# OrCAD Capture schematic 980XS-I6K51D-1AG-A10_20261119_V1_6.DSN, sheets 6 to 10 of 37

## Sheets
6 P0061_S6_POWER: size A2
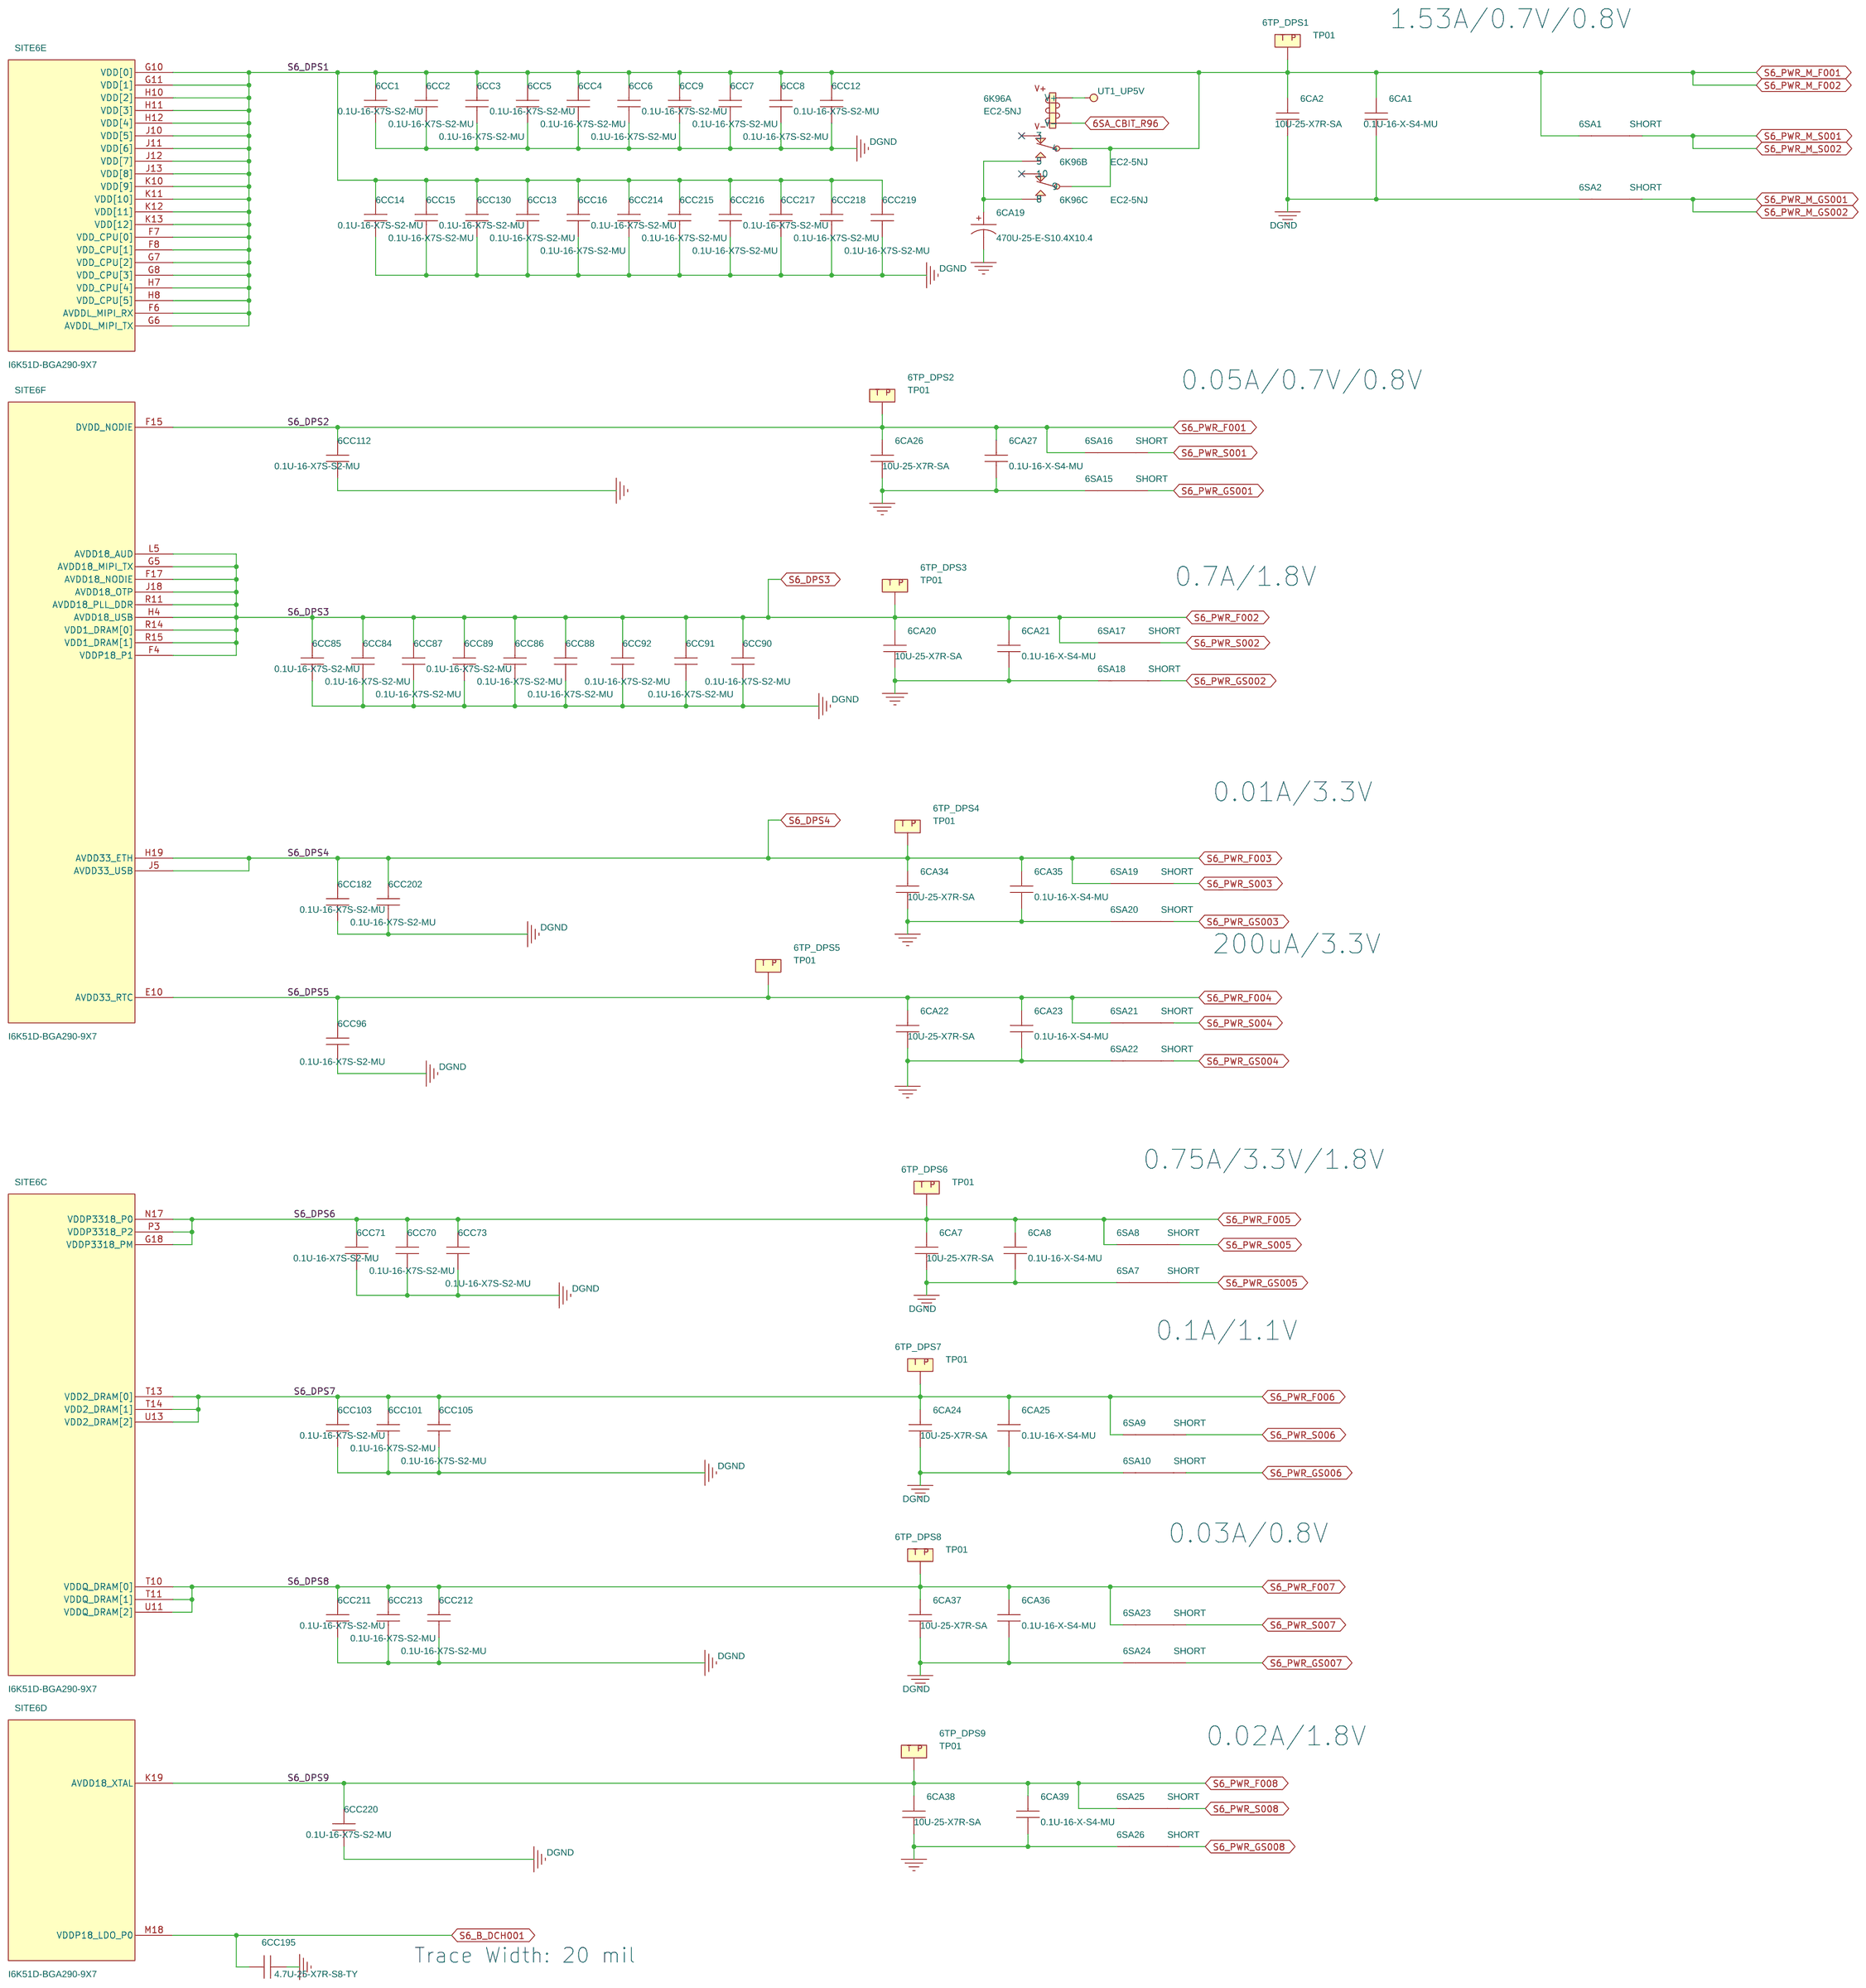
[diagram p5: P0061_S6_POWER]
7 P0053_S5_MIPI: size A2
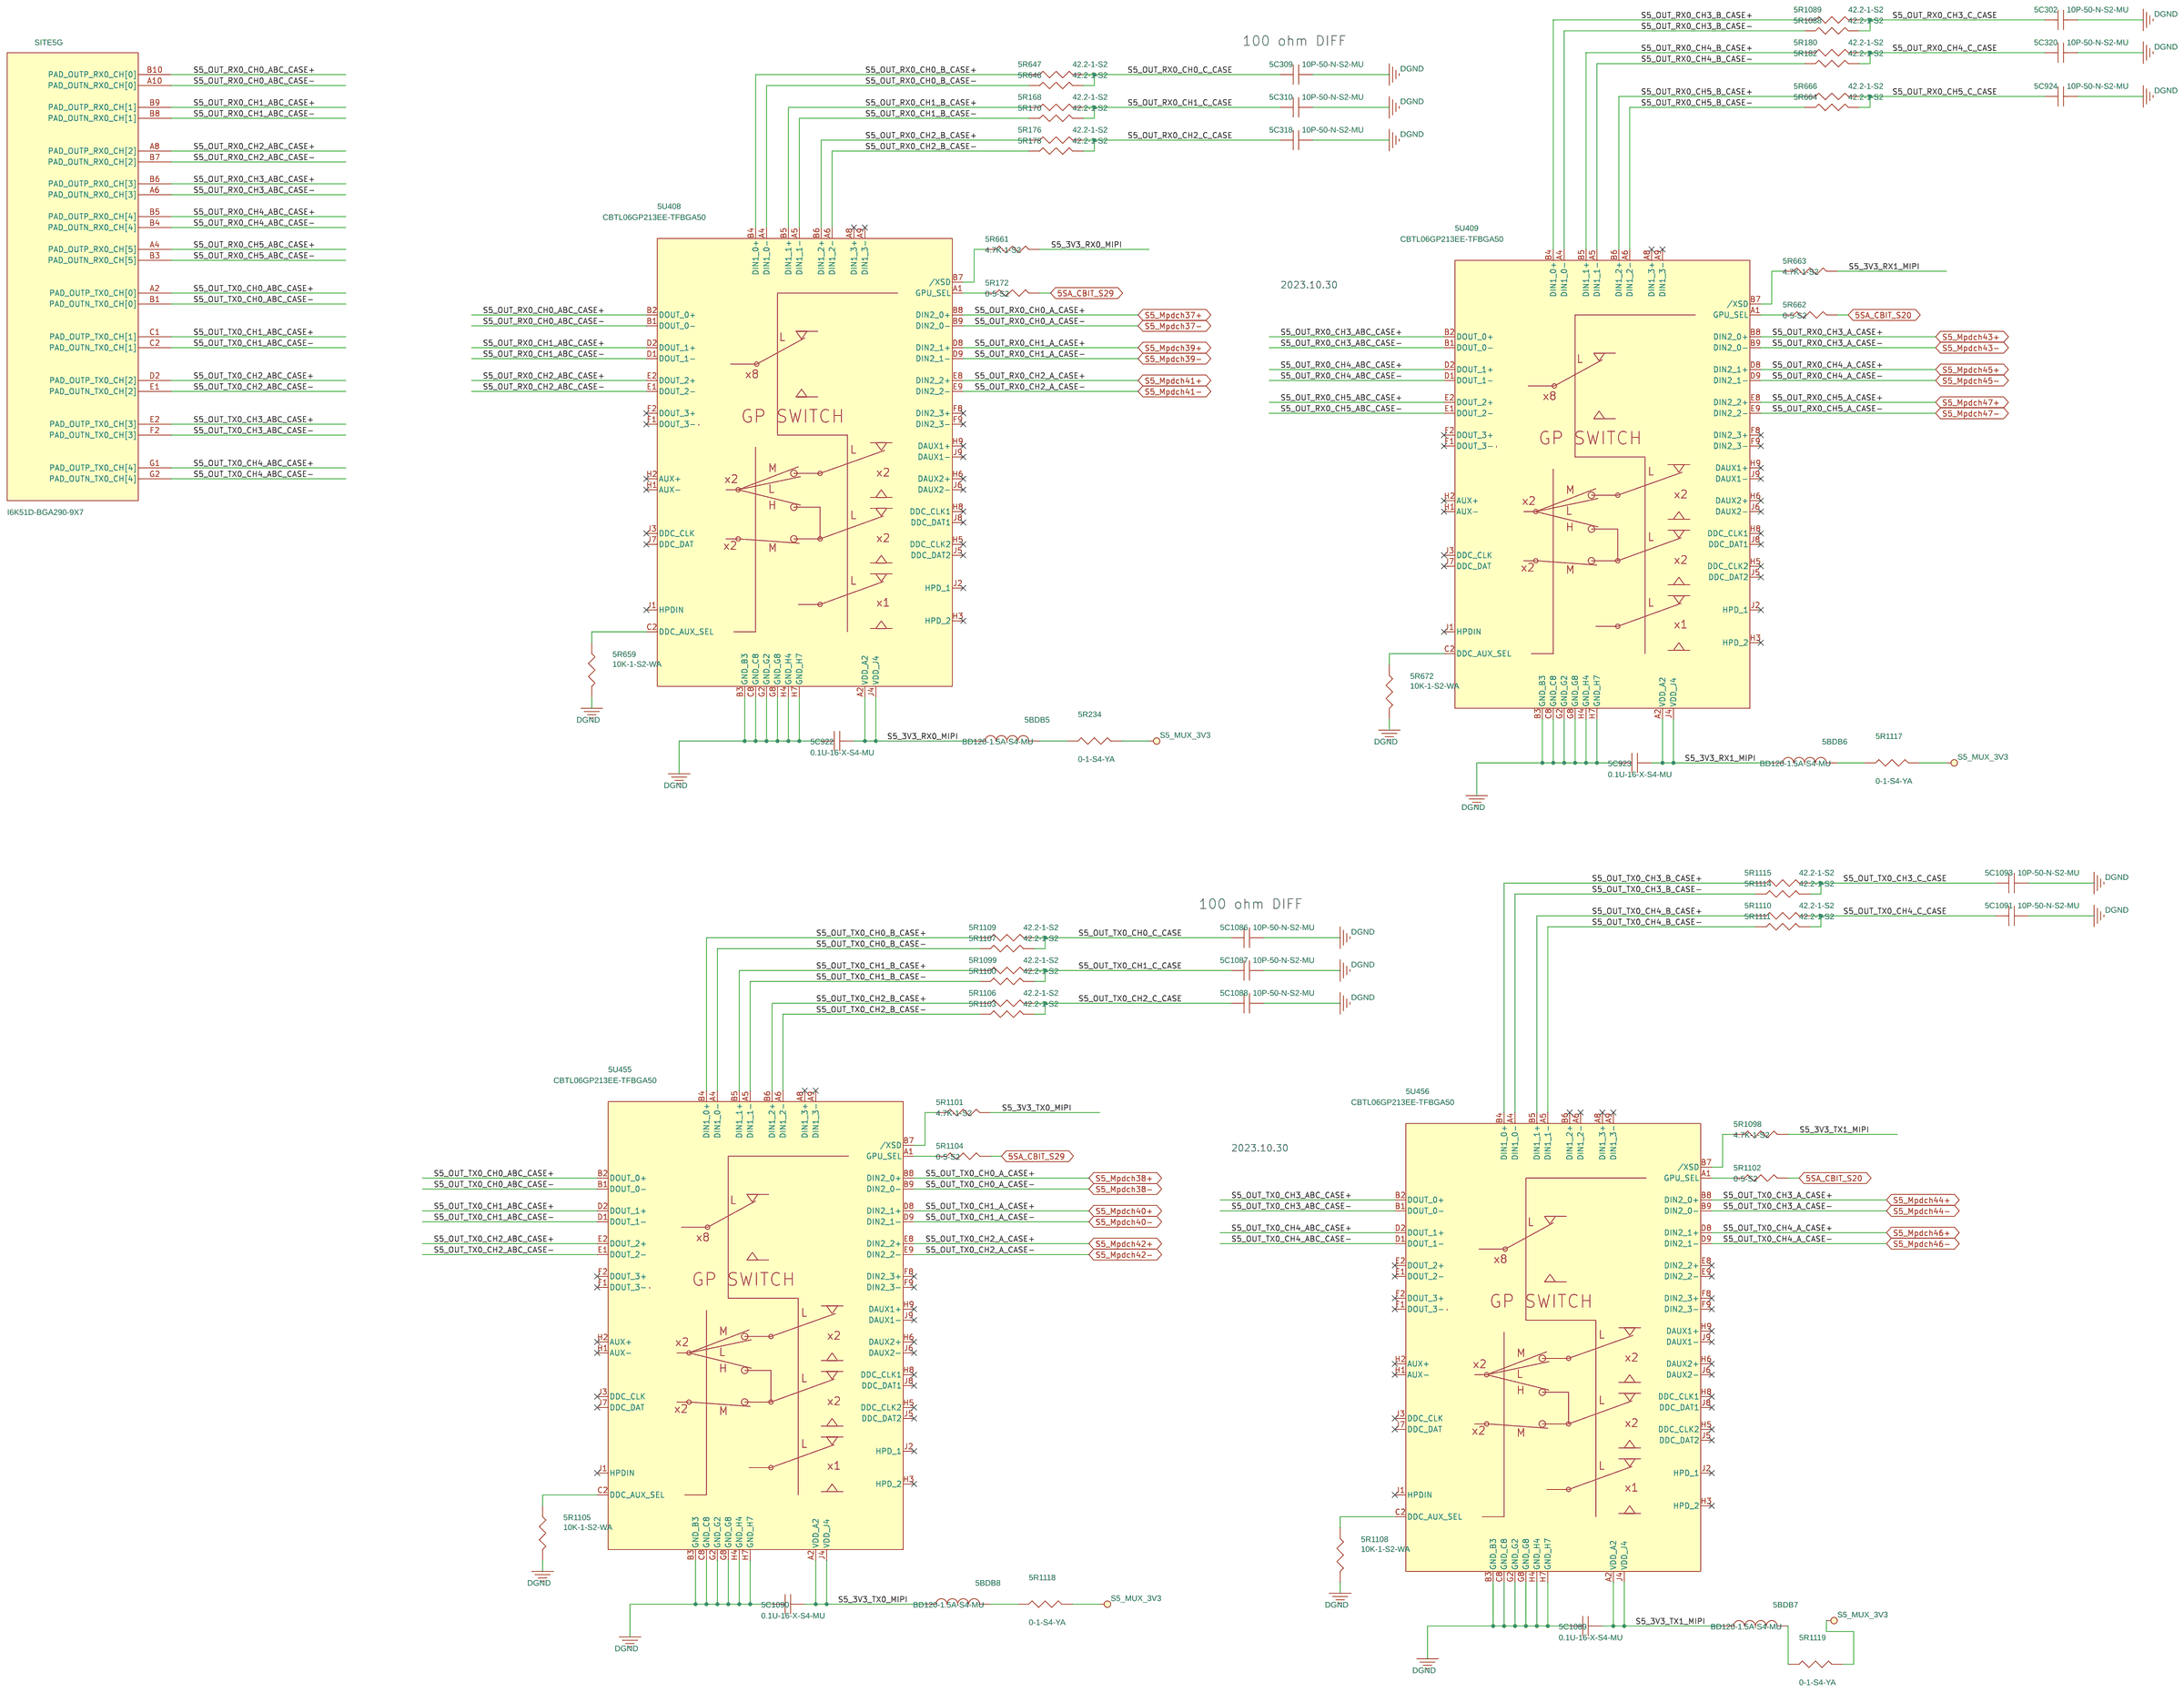
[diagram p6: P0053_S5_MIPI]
8 P0051_S5_POWER: size A2
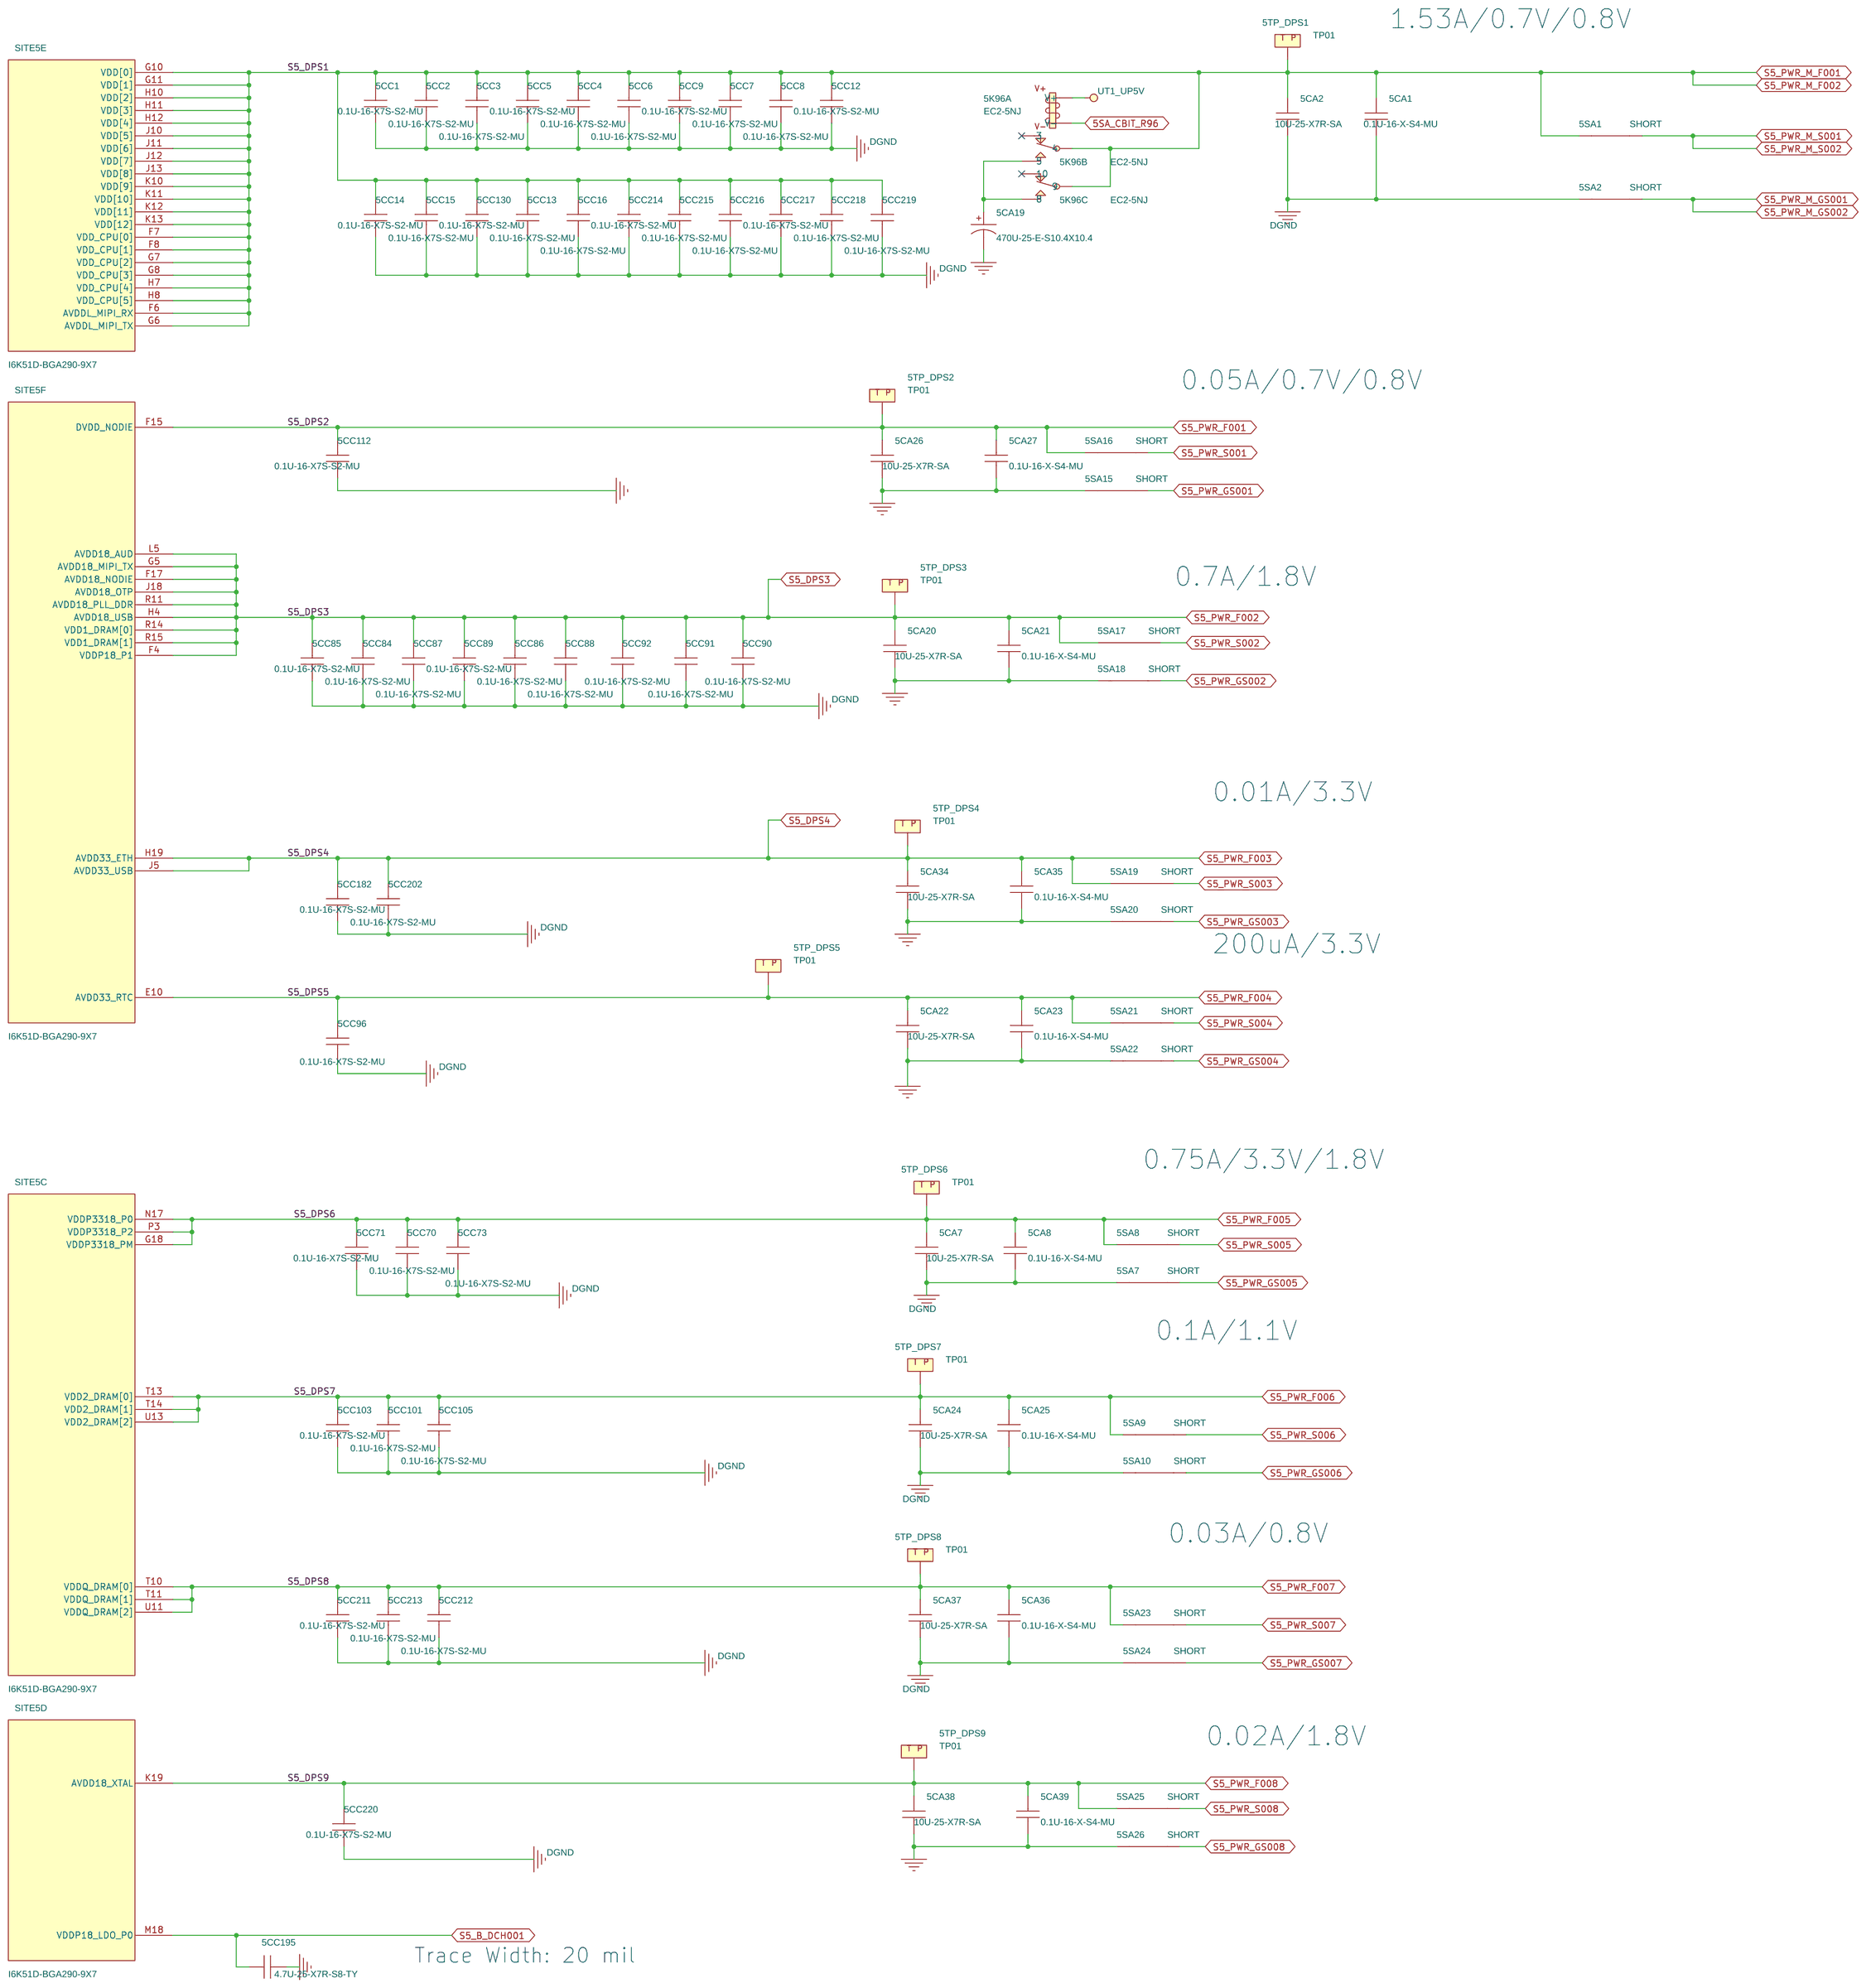
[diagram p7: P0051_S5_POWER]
9 P0043_S4_MIPI: size A2
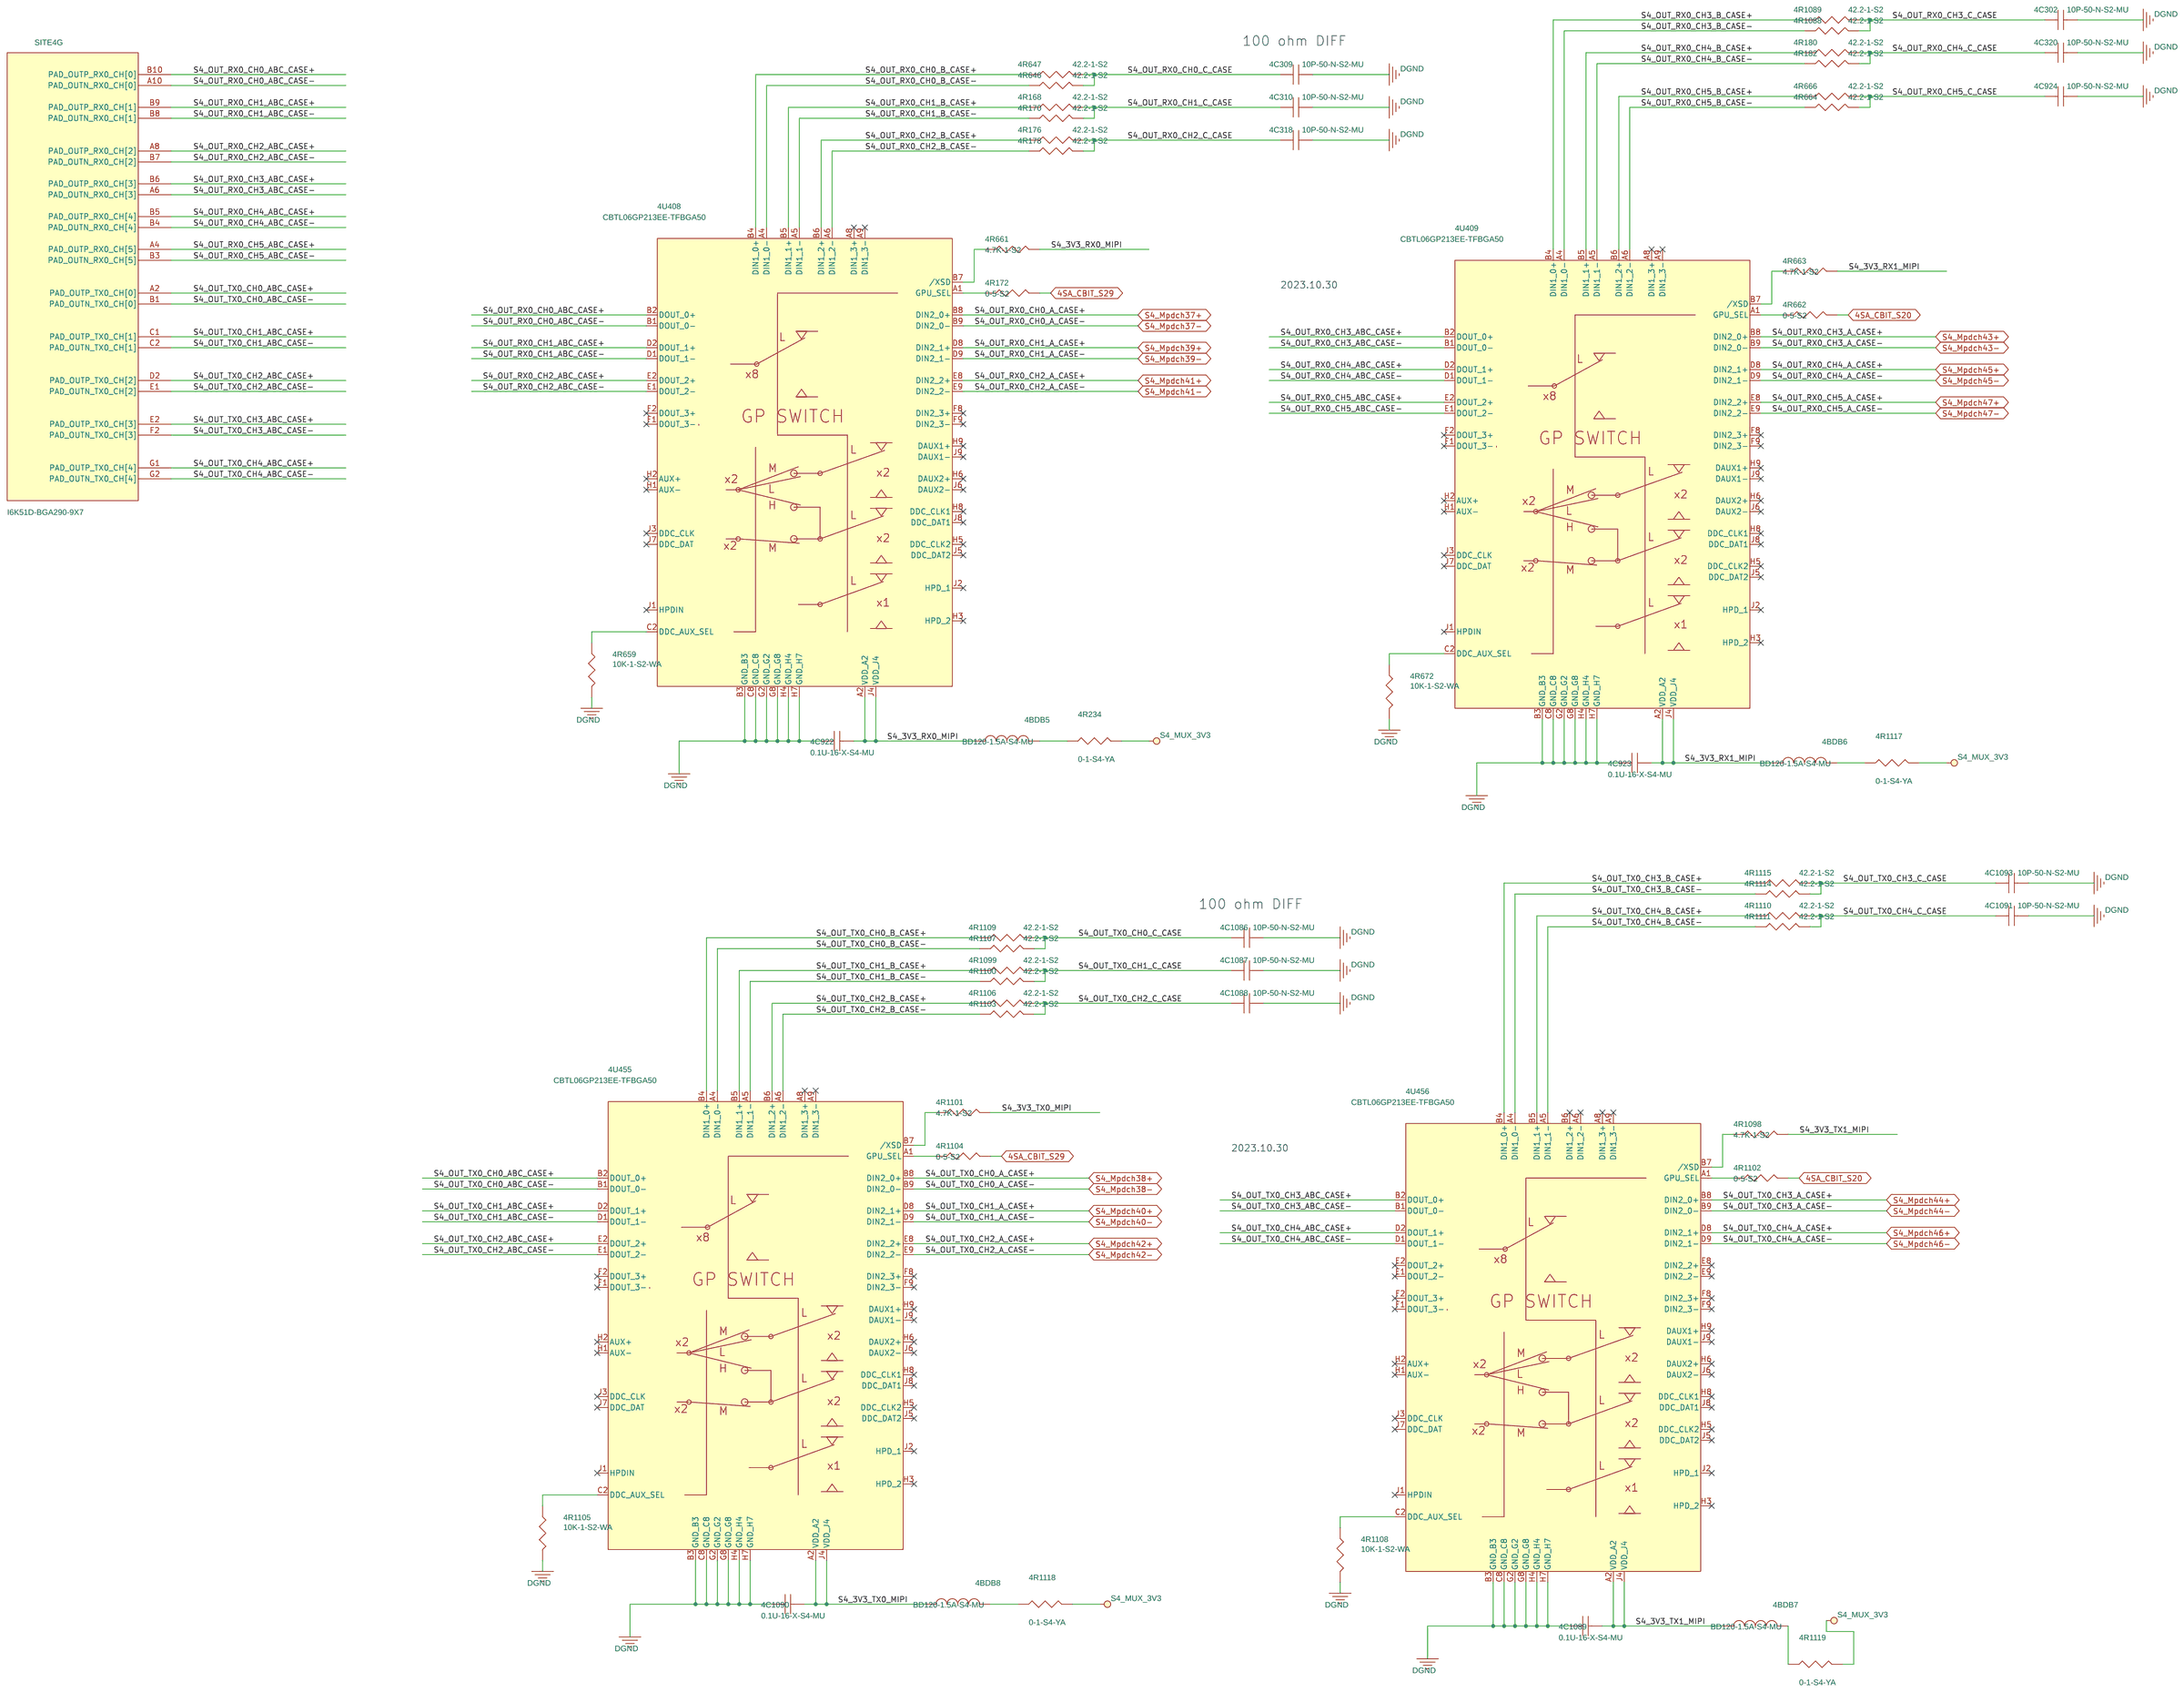
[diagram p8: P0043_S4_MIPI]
10 P0041_S4_POWER: size A2
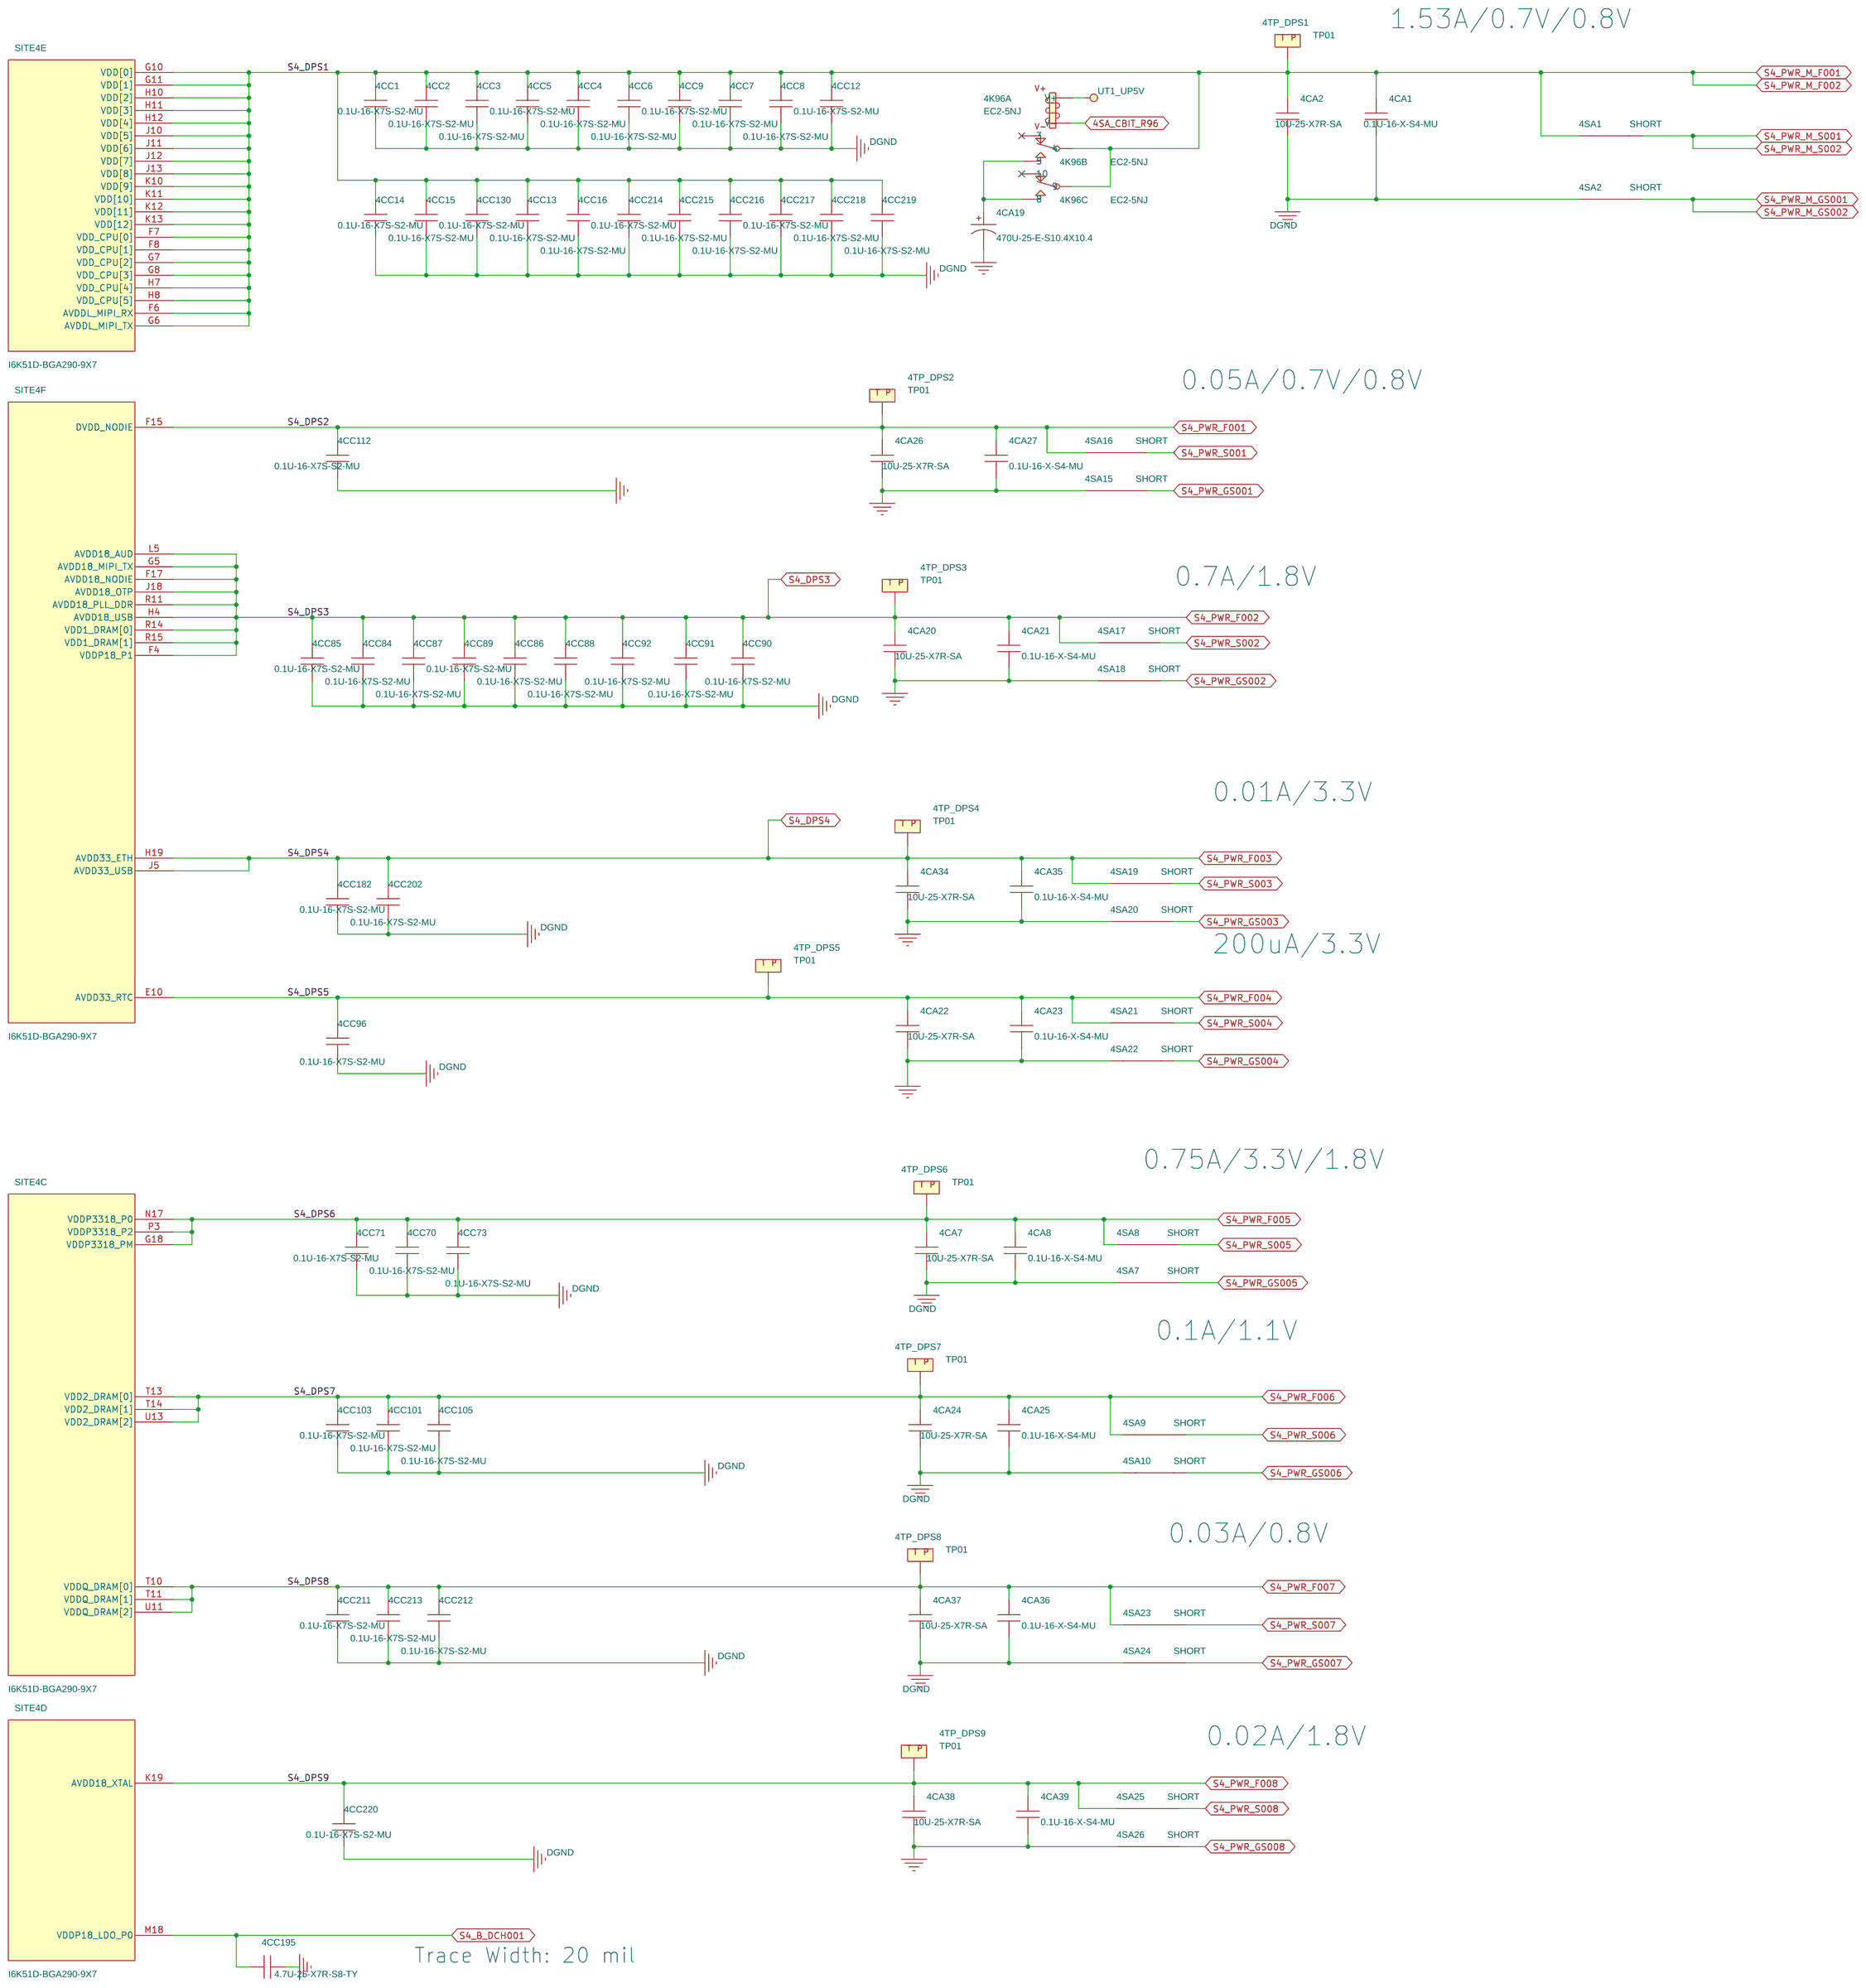
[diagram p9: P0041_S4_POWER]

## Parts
sheet P0041_S4_POWER
4CA1  0.1U-16-X-S4-MU  [C0402]
4CA2  10U-25-X7R-SA  [C1206]
4CA7  10U-25-X7R-SA  [C1206]
4CA8  0.1U-16-X-S4-MU  [C0402]
4CA19  470U-25-E-S10.4X10.4  [EC_10P3X10_S]
4CA20  10U-25-X7R-SA  [C1206]
4CA21  0.1U-16-X-S4-MU  [C0402]
4CA22  10U-25-X7R-SA  [C1206]
4CA23  0.1U-16-X-S4-MU  [C0402]
4CA24  10U-25-X7R-SA  [C1206]
4CA25  0.1U-16-X-S4-MU  [C0402]
4CA26  10U-25-X7R-SA  [C1206]
4CA27  0.1U-16-X-S4-MU  [C0402]
4CA34  10U-25-X7R-SA  [C1206]
4CA35  0.1U-16-X-S4-MU  [C0402]
4CA36  0.1U-16-X-S4-MU  [C0402]
4CA37  10U-25-X7R-SA  [C1206]
4CA38  10U-25-X7R-SA  [C1206]
4CA39  0.1U-16-X-S4-MU  [C0402]
4CC1  0.1U-16-X7S-S2-MU  [C0201_MINI]
4CC2  0.1U-16-X7S-S2-MU  [C0201_MINI]
4CC3  0.1U-16-X7S-S2-MU  [C0201_MINI]
4CC4  0.1U-16-X7S-S2-MU  [C0201_MINI]
4CC5  0.1U-16-X7S-S2-MU  [C0201_MINI]
4CC6  0.1U-16-X7S-S2-MU  [C0201_MINI]
4CC7  0.1U-16-X7S-S2-MU  [C0201_MINI]
4CC8  0.1U-16-X7S-S2-MU  [C0201_MINI]
4CC9  0.1U-16-X7S-S2-MU  [C0201_MINI]
4CC12  0.1U-16-X7S-S2-MU  [C0201_MINI]
4CC13  0.1U-16-X7S-S2-MU  [C0201_MINI]
4CC14  0.1U-16-X7S-S2-MU  [C0201_MINI]
4CC15  0.1U-16-X7S-S2-MU  [C0201_MINI]
4CC16  0.1U-16-X7S-S2-MU  [C0201_MINI]
4CC70  0.1U-16-X7S-S2-MU  [C0201_MINI]
4CC71  0.1U-16-X7S-S2-MU  [C0201_MINI]
4CC73  0.1U-16-X7S-S2-MU  [C0201_MINI]
4CC84  0.1U-16-X7S-S2-MU  [C0201_MINI]
4CC85  0.1U-16-X7S-S2-MU  [C0201_MINI]
4CC86  0.1U-16-X7S-S2-MU  [C0201_MINI]
4CC87  0.1U-16-X7S-S2-MU  [C0201_MINI]
4CC88  0.1U-16-X7S-S2-MU  [C0201_MINI]
4CC89  0.1U-16-X7S-S2-MU  [C0201_MINI]
4CC90  0.1U-16-X7S-S2-MU  [C0201_MINI]
4CC91  0.1U-16-X7S-S2-MU  [C0201_MINI]
4CC92  0.1U-16-X7S-S2-MU  [C0201_MINI]
4CC96  0.1U-16-X7S-S2-MU  [C0201_MINI]
4CC101  0.1U-16-X7S-S2-MU  [C0201_MINI]
4CC103  0.1U-16-X7S-S2-MU  [C0201_MINI]
4CC105  0.1U-16-X7S-S2-MU  [C0201_MINI]
4CC112  0.1U-16-X7S-S2-MU  [C0201_MINI]
4CC130  0.1U-16-X7S-S2-MU  [C0201_MINI]
4CC182  0.1U-16-X7S-S2-MU  [C0201_MINI]
4CC195  4.7U-25-X7R-S8-TY  [C0805]
4CC202  0.1U-16-X7S-S2-MU  [C0201_MINI]
4CC211  0.1U-16-X7S-S2-MU  [C0201_MINI]
4CC212  0.1U-16-X7S-S2-MU  [C0201_MINI]
4CC213  0.1U-16-X7S-S2-MU  [C0201_MINI]
4CC214  0.1U-16-X7S-S2-MU  [C0201_MINI]
4CC215  0.1U-16-X7S-S2-MU  [C0201_MINI]
4CC216  0.1U-16-X7S-S2-MU  [C0201_MINI]
4CC217  0.1U-16-X7S-S2-MU  [C0201_MINI]
4CC218  0.1U-16-X7S-S2-MU  [C0201_MINI]
4CC219  0.1U-16-X7S-S2-MU  [C0201_MINI]
4CC220  0.1U-16-X7S-S2-MU  [C0201_MINI]
4K96  EC2-5NJ  [RL_NECEC2_10P_5V]  (sections A,B,C)
4SA1  SHORT  [DEFAULT_SHORT_SMALL]
4SA2  SHORT  [DEFAULT_SHORT_SMALL]
4SA7  SHORT  [DEFAULT_SHORT_SMALL]
4SA8  SHORT  [DEFAULT_SHORT_SMALL]
4SA9  SHORT  [DEFAULT_SHORT_SMALL]
4SA10  SHORT  [DEFAULT_SHORT_SMALL]
4SA15  SHORT  [DEFAULT_SHORT_SMALL]
4SA16  SHORT  [DEFAULT_SHORT_SMALL]
4SA17  SHORT  [DEFAULT_SHORT_SMALL]
4SA18  SHORT  [DEFAULT_SHORT_SMALL]
4SA19  SHORT  [DEFAULT_SHORT_SMALL]
4SA20  SHORT  [DEFAULT_SHORT_SMALL]
4SA21  SHORT  [DEFAULT_SHORT_SMALL]
4SA22  SHORT  [DEFAULT_SHORT_SMALL]
4SA23  SHORT  [DEFAULT_SHORT_SMALL]
4SA24  SHORT  [DEFAULT_SHORT_SMALL]
4SA25  SHORT  [DEFAULT_SHORT_SMALL]
4SA26  SHORT  [DEFAULT_SHORT_SMALL]
4TP_DPS1  TP01  [TP_040_T]
4TP_DPS2  TP01  [TP_040_T]
4TP_DPS3  TP01  [TP_040_T]
4TP_DPS4  TP01  [TP_040_T]
4TP_DPS5  TP01  [TP_040_T]
4TP_DPS6  TP01  [TP_040_T]
4TP_DPS7  TP01  [TP_040_T]
4TP_DPS8  TP01  [TP_040_T]
4TP_DPS9  TP01  [TP_040_T]
SITE4  I6K51D-BGA290-9X7  [SK_TFBGA7X9_290P_0P4MM_JG]  (sections A,B,C,D,E,F,G,H,I,J,K,L,M,N,O)
sheet P0043_S4_MIPI
4BDB5  BD120-1.5A-S4-MU  [FB0402]
4BDB6  BD120-1.5A-S4-MU  [FB0402]
4BDB7  BD120-1.5A-S4-MU  [FB0402]
4BDB8  BD120-1.5A-S4-MU  [FB0402]
4C302  10P-50-N-S2-MU  [C0201]
4C309  10P-50-N-S2-MU  [C0201]
4C310  10P-50-N-S2-MU  [C0201]
4C318  10P-50-N-S2-MU  [C0201]
4C320  10P-50-N-S2-MU  [C0201]
4C922  0.1U-16-X-S4-MU  [C0402]
4C923  0.1U-16-X-S4-MU  [C0402]
4C924  10P-50-N-S2-MU  [C0201]
4C1086  10P-50-N-S2-MU  [C0201]
4C1087  10P-50-N-S2-MU  [C0201]
4C1088  10P-50-N-S2-MU  [C0201]
4C1089  0.1U-16-X-S4-MU  [C0402]
4C1090  0.1U-16-X-S4-MU  [C0402]
4C1091  10P-50-N-S2-MU  [C0201]
4C1093  10P-50-N-S2-MU  [C0201]
4R168  42.2-1-S2  [R0201]
4R170  42.2-1-S2  [R0201]
4R172  0-5-S2  [R0201]
4R176  42.2-1-S2  [R0201]
4R178  42.2-1-S2  [R0201]
4R180  42.2-1-S2  [R0201]
4R182  42.2-1-S2  [R0201]
4R234  0-1-S4-YA  [R0402]
4R646  42.2-1-S2  [R0201]
4R647  42.2-1-S2  [R0201]
4R659  10K-1-S2-WA  [R0201]
4R661  4.7K-1-S2  [R0201]
4R662  0-5-S2  [R0201]
4R663  4.7K-1-S2  [R0201]
4R664  42.2-1-S2  [R0201]
4R666  42.2-1-S2  [R0201]
4R672  10K-1-S2-WA  [R0201]
4R1088  42.2-1-S2  [R0201]
4R1089  42.2-1-S2  [R0201]
4R1098  4.7K-1-S2  [R0201]
4R1099  42.2-1-S2  [R0201]
4R1100  42.2-1-S2  [R0201]
4R1101  4.7K-1-S2  [R0201]
4R1102  0-5-S2  [R0201]
4R1103  42.2-1-S2  [R0201]
4R1104  0-5-S2  [R0201]
4R1105  10K-1-S2-WA  [R0201]
4R1106  42.2-1-S2  [R0201]
4R1107  42.2-1-S2  [R0201]
4R1108  10K-1-S2-WA  [R0201]
4R1109  42.2-1-S2  [R0201]
4R1110  42.2-1-S2  [R0201]
4R1111  42.2-1-S2  [R0201]
4R1114  42.2-1-S2  [R0201]
4R1115  42.2-1-S2  [R0201]
4R1117  0-1-S4-YA  [R0402]
4R1118  0-1-S4-YA  [R0402]
4R1119  0-1-S4-YA  [R0402]
4U408  CBTL06GP213EE-TFBGA50  [TFBGA9X9_50P_0P5MM]
4U409  CBTL06GP213EE-TFBGA50  [TFBGA9X9_50P_0P5MM]
4U455  CBTL06GP213EE-TFBGA50  [TFBGA9X9_50P_0P5MM]
4U456  CBTL06GP213EE-TFBGA50  [TFBGA9X9_50P_0P5MM]
sheet P0051_S5_POWER
5CA1  0.1U-16-X-S4-MU  [C0402]
5CA2  10U-25-X7R-SA  [C1206]
5CA7  10U-25-X7R-SA  [C1206]
5CA8  0.1U-16-X-S4-MU  [C0402]
5CA19  470U-25-E-S10.4X10.4  [EC_10P3X10_S]
5CA20  10U-25-X7R-SA  [C1206]
5CA21  0.1U-16-X-S4-MU  [C0402]
5CA22  10U-25-X7R-SA  [C1206]
5CA23  0.1U-16-X-S4-MU  [C0402]
5CA24  10U-25-X7R-SA  [C1206]
5CA25  0.1U-16-X-S4-MU  [C0402]
5CA26  10U-25-X7R-SA  [C1206]
5CA27  0.1U-16-X-S4-MU  [C0402]
5CA34  10U-25-X7R-SA  [C1206]
5CA35  0.1U-16-X-S4-MU  [C0402]
5CA36  0.1U-16-X-S4-MU  [C0402]
5CA37  10U-25-X7R-SA  [C1206]
5CA38  10U-25-X7R-SA  [C1206]
5CA39  0.1U-16-X-S4-MU  [C0402]
5CC1  0.1U-16-X7S-S2-MU  [C0201_MINI]
5CC2  0.1U-16-X7S-S2-MU  [C0201_MINI]
5CC3  0.1U-16-X7S-S2-MU  [C0201_MINI]
5CC4  0.1U-16-X7S-S2-MU  [C0201_MINI]
5CC5  0.1U-16-X7S-S2-MU  [C0201_MINI]
5CC6  0.1U-16-X7S-S2-MU  [C0201_MINI]
5CC7  0.1U-16-X7S-S2-MU  [C0201_MINI]
5CC8  0.1U-16-X7S-S2-MU  [C0201_MINI]
5CC9  0.1U-16-X7S-S2-MU  [C0201_MINI]
5CC12  0.1U-16-X7S-S2-MU  [C0201_MINI]
5CC13  0.1U-16-X7S-S2-MU  [C0201_MINI]
5CC14  0.1U-16-X7S-S2-MU  [C0201_MINI]
5CC15  0.1U-16-X7S-S2-MU  [C0201_MINI]
5CC16  0.1U-16-X7S-S2-MU  [C0201_MINI]
5CC70  0.1U-16-X7S-S2-MU  [C0201_MINI]
5CC71  0.1U-16-X7S-S2-MU  [C0201_MINI]
5CC73  0.1U-16-X7S-S2-MU  [C0201_MINI]
5CC84  0.1U-16-X7S-S2-MU  [C0201_MINI]
5CC85  0.1U-16-X7S-S2-MU  [C0201_MINI]
5CC86  0.1U-16-X7S-S2-MU  [C0201_MINI]
5CC87  0.1U-16-X7S-S2-MU  [C0201_MINI]
5CC88  0.1U-16-X7S-S2-MU  [C0201_MINI]
5CC89  0.1U-16-X7S-S2-MU  [C0201_MINI]
5CC90  0.1U-16-X7S-S2-MU  [C0201_MINI]
5CC91  0.1U-16-X7S-S2-MU  [C0201_MINI]
5CC92  0.1U-16-X7S-S2-MU  [C0201_MINI]
5CC96  0.1U-16-X7S-S2-MU  [C0201_MINI]
5CC101  0.1U-16-X7S-S2-MU  [C0201_MINI]
5CC103  0.1U-16-X7S-S2-MU  [C0201_MINI]
5CC105  0.1U-16-X7S-S2-MU  [C0201_MINI]
5CC112  0.1U-16-X7S-S2-MU  [C0201_MINI]
5CC130  0.1U-16-X7S-S2-MU  [C0201_MINI]
5CC182  0.1U-16-X7S-S2-MU  [C0201_MINI]
5CC195  4.7U-25-X7R-S8-TY  [C0805]
5CC202  0.1U-16-X7S-S2-MU  [C0201_MINI]
5CC211  0.1U-16-X7S-S2-MU  [C0201_MINI]
5CC212  0.1U-16-X7S-S2-MU  [C0201_MINI]
5CC213  0.1U-16-X7S-S2-MU  [C0201_MINI]
5CC214  0.1U-16-X7S-S2-MU  [C0201_MINI]
5CC215  0.1U-16-X7S-S2-MU  [C0201_MINI]
5CC216  0.1U-16-X7S-S2-MU  [C0201_MINI]
5CC217  0.1U-16-X7S-S2-MU  [C0201_MINI]
5CC218  0.1U-16-X7S-S2-MU  [C0201_MINI]
5CC219  0.1U-16-X7S-S2-MU  [C0201_MINI]
5CC220  0.1U-16-X7S-S2-MU  [C0201_MINI]
5K96  EC2-5NJ  [RL_NECEC2_10P_5V]  (sections A,B,C)
5SA1  SHORT  [DEFAULT_SHORT_SMALL]
5SA2  SHORT  [DEFAULT_SHORT_SMALL]
5SA7  SHORT  [DEFAULT_SHORT_SMALL]
5SA8  SHORT  [DEFAULT_SHORT_SMALL]
5SA9  SHORT  [DEFAULT_SHORT_SMALL]
5SA10  SHORT  [DEFAULT_SHORT_SMALL]
5SA15  SHORT  [DEFAULT_SHORT_SMALL]
5SA16  SHORT  [DEFAULT_SHORT_SMALL]
5SA17  SHORT  [DEFAULT_SHORT_SMALL]
5SA18  SHORT  [DEFAULT_SHORT_SMALL]
5SA19  SHORT  [DEFAULT_SHORT_SMALL]
5SA20  SHORT  [DEFAULT_SHORT_SMALL]
5SA21  SHORT  [DEFAULT_SHORT_SMALL]
5SA22  SHORT  [DEFAULT_SHORT_SMALL]
5SA23  SHORT  [DEFAULT_SHORT_SMALL]
5SA24  SHORT  [DEFAULT_SHORT_SMALL]
5SA25  SHORT  [DEFAULT_SHORT_SMALL]
5SA26  SHORT  [DEFAULT_SHORT_SMALL]
5TP_DPS1  TP01  [TP_040_T]
5TP_DPS2  TP01  [TP_040_T]
5TP_DPS3  TP01  [TP_040_T]
5TP_DPS4  TP01  [TP_040_T]
5TP_DPS5  TP01  [TP_040_T]
5TP_DPS6  TP01  [TP_040_T]
5TP_DPS7  TP01  [TP_040_T]
5TP_DPS8  TP01  [TP_040_T]
5TP_DPS9  TP01  [TP_040_T]
sheet P0052_S5_USB/AUD/FLASH/XTAL
SITE5  I6K51D-BGA290-9X7  [SK_TFBGA7X9_290P_0P4MM_JG]  (sections A,B,C,D,E,F,G,H,I,J,K,L,M,N,O)
sheet P0053_S5_MIPI
5BDB5  BD120-1.5A-S4-MU  [FB0402]
5BDB6  BD120-1.5A-S4-MU  [FB0402]
5BDB7  BD120-1.5A-S4-MU  [FB0402]
5BDB8  BD120-1.5A-S4-MU  [FB0402]
5C302  10P-50-N-S2-MU  [C0201]
5C309  10P-50-N-S2-MU  [C0201]
5C310  10P-50-N-S2-MU  [C0201]
5C318  10P-50-N-S2-MU  [C0201]
5C320  10P-50-N-S2-MU  [C0201]
5C922  0.1U-16-X-S4-MU  [C0402]
5C923  0.1U-16-X-S4-MU  [C0402]
5C924  10P-50-N-S2-MU  [C0201]
5C1086  10P-50-N-S2-MU  [C0201]
5C1087  10P-50-N-S2-MU  [C0201]
5C1088  10P-50-N-S2-MU  [C0201]
5C1089  0.1U-16-X-S4-MU  [C0402]
5C1090  0.1U-16-X-S4-MU  [C0402]
5C1091  10P-50-N-S2-MU  [C0201]
5C1093  10P-50-N-S2-MU  [C0201]
5R168  42.2-1-S2  [R0201]
5R170  42.2-1-S2  [R0201]
5R172  0-5-S2  [R0201]
5R176  42.2-1-S2  [R0201]
5R178  42.2-1-S2  [R0201]
5R180  42.2-1-S2  [R0201]
5R182  42.2-1-S2  [R0201]
5R234  0-1-S4-YA  [R0402]
5R646  42.2-1-S2  [R0201]
5R647  42.2-1-S2  [R0201]
5R659  10K-1-S2-WA  [R0201]
5R661  4.7K-1-S2  [R0201]
5R662  0-5-S2  [R0201]
5R663  4.7K-1-S2  [R0201]
5R664  42.2-1-S2  [R0201]
5R666  42.2-1-S2  [R0201]
5R672  10K-1-S2-WA  [R0201]
5R1088  42.2-1-S2  [R0201]
5R1089  42.2-1-S2  [R0201]
5R1098  4.7K-1-S2  [R0201]
5R1099  42.2-1-S2  [R0201]
5R1100  42.2-1-S2  [R0201]
5R1101  4.7K-1-S2  [R0201]
5R1102  0-5-S2  [R0201]
5R1103  42.2-1-S2  [R0201]
5R1104  0-5-S2  [R0201]
5R1105  10K-1-S2-WA  [R0201]
5R1106  42.2-1-S2  [R0201]
5R1107  42.2-1-S2  [R0201]
5R1108  10K-1-S2-WA  [R0201]
5R1109  42.2-1-S2  [R0201]
5R1110  42.2-1-S2  [R0201]
5R1111  42.2-1-S2  [R0201]
5R1114  42.2-1-S2  [R0201]
5R1115  42.2-1-S2  [R0201]
5R1117  0-1-S4-YA  [R0402]
5R1118  0-1-S4-YA  [R0402]
5R1119  0-1-S4-YA  [R0402]
5U408  CBTL06GP213EE-TFBGA50  [TFBGA9X9_50P_0P5MM]
5U409  CBTL06GP213EE-TFBGA50  [TFBGA9X9_50P_0P5MM]
5U455  CBTL06GP213EE-TFBGA50  [TFBGA9X9_50P_0P5MM]
5U456  CBTL06GP213EE-TFBGA50  [TFBGA9X9_50P_0P5MM]
sheet P0061_S6_POWER
6CA1  0.1U-16-X-S4-MU  [C0402]
6CA2  10U-25-X7R-SA  [C1206]
6CA7  10U-25-X7R-SA  [C1206]
6CA8  0.1U-16-X-S4-MU  [C0402]
6CA19  470U-25-E-S10.4X10.4  [EC_10P3X10_S]
6CA20  10U-25-X7R-SA  [C1206]
6CA21  0.1U-16-X-S4-MU  [C0402]
6CA22  10U-25-X7R-SA  [C1206]
6CA23  0.1U-16-X-S4-MU  [C0402]
6CA24  10U-25-X7R-SA  [C1206]
6CA25  0.1U-16-X-S4-MU  [C0402]
6CA26  10U-25-X7R-SA  [C1206]
6CA27  0.1U-16-X-S4-MU  [C0402]
6CA34  10U-25-X7R-SA  [C1206]
6CA35  0.1U-16-X-S4-MU  [C0402]
6CA36  0.1U-16-X-S4-MU  [C0402]
6CA37  10U-25-X7R-SA  [C1206]
6CA38  10U-25-X7R-SA  [C1206]
6CA39  0.1U-16-X-S4-MU  [C0402]
6CC1  0.1U-16-X7S-S2-MU  [C0201_MINI]
6CC2  0.1U-16-X7S-S2-MU  [C0201_MINI]
6CC3  0.1U-16-X7S-S2-MU  [C0201_MINI]
6CC4  0.1U-16-X7S-S2-MU  [C0201_MINI]
6CC5  0.1U-16-X7S-S2-MU  [C0201_MINI]
6CC6  0.1U-16-X7S-S2-MU  [C0201_MINI]
6CC7  0.1U-16-X7S-S2-MU  [C0201_MINI]
6CC8  0.1U-16-X7S-S2-MU  [C0201_MINI]
6CC9  0.1U-16-X7S-S2-MU  [C0201_MINI]
6CC12  0.1U-16-X7S-S2-MU  [C0201_MINI]
6CC13  0.1U-16-X7S-S2-MU  [C0201_MINI]
6CC14  0.1U-16-X7S-S2-MU  [C0201_MINI]
6CC15  0.1U-16-X7S-S2-MU  [C0201_MINI]
6CC16  0.1U-16-X7S-S2-MU  [C0201_MINI]
6CC70  0.1U-16-X7S-S2-MU  [C0201_MINI]
6CC71  0.1U-16-X7S-S2-MU  [C0201_MINI]
6CC73  0.1U-16-X7S-S2-MU  [C0201_MINI]
6CC84  0.1U-16-X7S-S2-MU  [C0201_MINI]
6CC85  0.1U-16-X7S-S2-MU  [C0201_MINI]
6CC86  0.1U-16-X7S-S2-MU  [C0201_MINI]
6CC87  0.1U-16-X7S-S2-MU  [C0201_MINI]
6CC88  0.1U-16-X7S-S2-MU  [C0201_MINI]
6CC89  0.1U-16-X7S-S2-MU  [C0201_MINI]
6CC90  0.1U-16-X7S-S2-MU  [C0201_MINI]
6CC91  0.1U-16-X7S-S2-MU  [C0201_MINI]
6CC92  0.1U-16-X7S-S2-MU  [C0201_MINI]
6CC96  0.1U-16-X7S-S2-MU  [C0201_MINI]
6CC101  0.1U-16-X7S-S2-MU  [C0201_MINI]
6CC103  0.1U-16-X7S-S2-MU  [C0201_MINI]
6CC105  0.1U-16-X7S-S2-MU  [C0201_MINI]
6CC112  0.1U-16-X7S-S2-MU  [C0201_MINI]
6CC130  0.1U-16-X7S-S2-MU  [C0201_MINI]
6CC182  0.1U-16-X7S-S2-MU  [C0201_MINI]
6CC195  4.7U-25-X7R-S8-TY  [C0805]
6CC202  0.1U-16-X7S-S2-MU  [C0201_MINI]
6CC211  0.1U-16-X7S-S2-MU  [C0201_MINI]
6CC212  0.1U-16-X7S-S2-MU  [C0201_MINI]
6CC213  0.1U-16-X7S-S2-MU  [C0201_MINI]
6CC214  0.1U-16-X7S-S2-MU  [C0201_MINI]
6CC215  0.1U-16-X7S-S2-MU  [C0201_MINI]
6CC216  0.1U-16-X7S-S2-MU  [C0201_MINI]
6CC217  0.1U-16-X7S-S2-MU  [C0201_MINI]
6CC218  0.1U-16-X7S-S2-MU  [C0201_MINI]
6CC219  0.1U-16-X7S-S2-MU  [C0201_MINI]
6CC220  0.1U-16-X7S-S2-MU  [C0201_MINI]
6K96  EC2-5NJ  [RL_NECEC2_10P_5V]  (sections A,B,C)
6SA1  SHORT  [DEFAULT_SHORT_SMALL]
6SA2  SHORT  [DEFAULT_SHORT_SMALL]
6SA7  SHORT  [DEFAULT_SHORT_SMALL]
6SA8  SHORT  [DEFAULT_SHORT_SMALL]
6SA9  SHORT  [DEFAULT_SHORT_SMALL]
6SA10  SHORT  [DEFAULT_SHORT_SMALL]
6SA15  SHORT  [DEFAULT_SHORT_SMALL]
6SA16  SHORT  [DEFAULT_SHORT_SMALL]
6SA17  SHORT  [DEFAULT_SHORT_SMALL]
6SA18  SHORT  [DEFAULT_SHORT_SMALL]
6SA19  SHORT  [DEFAULT_SHORT_SMALL]
6SA20  SHORT  [DEFAULT_SHORT_SMALL]
6SA21  SHORT  [DEFAULT_SHORT_SMALL]
6SA22  SHORT  [DEFAULT_SHORT_SMALL]
6SA23  SHORT  [DEFAULT_SHORT_SMALL]
6SA24  SHORT  [DEFAULT_SHORT_SMALL]
6SA25  SHORT  [DEFAULT_SHORT_SMALL]
6SA26  SHORT  [DEFAULT_SHORT_SMALL]
6TP_DPS1  TP01  [TP_040_T]
6TP_DPS2  TP01  [TP_040_T]
6TP_DPS3  TP01  [TP_040_T]
6TP_DPS4  TP01  [TP_040_T]
6TP_DPS5  TP01  [TP_040_T]
6TP_DPS6  TP01  [TP_040_T]
6TP_DPS7  TP01  [TP_040_T]
6TP_DPS8  TP01  [TP_040_T]
6TP_DPS9  TP01  [TP_040_T]
sheet P0062_S6_USB/AUD/FLASH/XTAL
SITE6  I6K51D-BGA290-9X7  [SK_TFBGA7X9_290P_0P4MM_JG]  (sections A,B,C,D,E,F,G,H,I,J,K,L,M,N,O)

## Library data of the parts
4CA1 5CA1 6CA1 = 0.1U-16-X-S4-MU: KAIROSNAME: CA1
4CA2 5CA2 6CA2 = 10U-25-X7R-SA: KAIROSNAME: CA2
4CA7 5CA7 6CA7 = 10U-25-X7R-SA: KAIROSNAME: CA7
4CA8 5CA8 6CA8 = 0.1U-16-X-S4-MU: KAIROSNAME: CA8
4CA19 5CA19 6CA19 = 470U-25-E-S10.4X10.4: KAIROSNAME: CA19
4CA20 4CA34 4CA38 5CA20 5CA34 5CA38 6CA20 6CA34 6CA38 = 10U-25-X7R-SA: KAIROSNAME: CA20
4CA21 4CA35 4CA39 5CA21 5CA35 5CA39 6CA21 6CA35 6CA39 = 0.1U-16-X-S4-MU: KAIROSNAME: CA21
4CA22 5CA22 6CA22 = 10U-25-X7R-SA: KAIROSNAME: CA22
4CA23 5CA23 6CA23 = 0.1U-16-X-S4-MU: KAIROSNAME: CA23
4CA24 4CA37 5CA24 5CA37 6CA24 6CA37 = 10U-25-X7R-SA: KAIROSNAME: CA24
4CA25 4CA36 5CA25 5CA36 6CA25 6CA36 = 0.1U-16-X-S4-MU: KAIROSNAME: CA25
4CA26 5CA26 6CA26 = 10U-25-X7R-SA: KAIROSNAME: CA26
4CA27 5CA27 6CA27 = 0.1U-16-X-S4-MU: KAIROSNAME: CA27
4CC1 4CC14 4CC16 4CC130 4CC214-4CC219 5CC1 5CC14 5CC16 5CC130 5CC214-5CC219 6CC1 6CC14 6CC16 6CC130 6CC214-6CC219 = 0.1U-16-X7S-S2-MU: KAIROSNAME: CC1
4CC2 4CC13 4CC15 5CC2 5CC13 5CC15 6CC2 6CC13 6CC15 = 0.1U-16-X7S-S2-MU: KAIROSNAME: CC2
4CC3 5CC3 6CC3 = 0.1U-16-X7S-S2-MU: KAIROSNAME: CC3
4CC4 5CC4 6CC4 = 0.1U-16-X7S-S2-MU: KAIROSNAME: CC4
4CC5 5CC5 6CC5 = 0.1U-16-X7S-S2-MU: KAIROSNAME: CC5
4CC6 5CC6 6CC6 = 0.1U-16-X7S-S2-MU: KAIROSNAME: CC6
4CC7 5CC7 6CC7 = 0.1U-16-X7S-S2-MU: KAIROSNAME: CC7
4CC8 5CC8 6CC8 = 0.1U-16-X7S-S2-MU: KAIROSNAME: CC8
4CC9 5CC9 6CC9 = 0.1U-16-X7S-S2-MU: KAIROSNAME: CC9
4CC12 5CC12 6CC12 = 0.1U-16-X7S-S2-MU: KAIROSNAME: CC12
4CC70 5CC70 6CC70 = 0.1U-16-X7S-S2-MU: KAIROSNAME: CC70
4CC71 5CC71 6CC71 = 0.1U-16-X7S-S2-MU: KAIROSNAME: CC71
4CC73 5CC73 6CC73 = 0.1U-16-X7S-S2-MU: KAIROSNAME: CC73
4CC84 5CC84 6CC84 = 0.1U-16-X7S-S2-MU: KAIROSNAME: CC84
4CC85 4CC182 4CC202 4CC220 5CC85 5CC182 5CC202 5CC220 6CC85 6CC182 6CC202 6CC220 = 0.1U-16-X7S-S2-MU: KAIROSNAME: CC85
4CC86 5CC86 6CC86 = 0.1U-16-X7S-S2-MU: KAIROSNAME: CC86
4CC87 5CC87 6CC87 = 0.1U-16-X7S-S2-MU: KAIROSNAME: CC87
4CC88 4CC90-4CC92 5CC88 5CC90-5CC92 6CC88 6CC90-6CC92 = 0.1U-16-X7S-S2-MU: KAIROSNAME: CC88
4CC89 5CC89 6CC89 = 0.1U-16-X7S-S2-MU: KAIROSNAME: CC89
4CC96 5CC96 6CC96 = 0.1U-16-X7S-S2-MU: KAIROSNAME: CC96
4CC101 4CC213 5CC101 5CC213 6CC101 6CC213 = 0.1U-16-X7S-S2-MU: KAIROSNAME: CC101
4CC103 4CC211 5CC103 5CC211 6CC103 6CC211 = 0.1U-16-X7S-S2-MU: KAIROSNAME: CC103
4CC105 4CC212 5CC105 5CC212 6CC105 6CC212 = 0.1U-16-X7S-S2-MU: KAIROSNAME: CC105
4CC112 5CC112 6CC112 = 0.1U-16-X7S-S2-MU: KAIROSNAME: CC112
4CC195 5CC195 6CC195 = 4.7U-25-X7R-S8-TY
4K96 5K96 6K96 = EC2-5NJ: KAIROSNAME: K95A
4SA1 4SA16 4SA17 4SA19 4SA21 4SA25 5SA1 5SA16 5SA17 5SA19 5SA21 5SA25 6SA1 6SA16 6SA17 6SA19 6SA21 6SA25 = SHORT: KAIROSNAME: SA1
4SA2 4SA15 4SA18 4SA20 4SA22 4SA26 5SA2 5SA15 5SA18 5SA20 5SA22 5SA26 6SA2 6SA15 6SA18 6SA20 6SA22 6SA26 = SHORT: KAIROSNAME: SA2
4SA7 5SA7 6SA7 = SHORT: KAIROSNAME: SA7
4SA8 5SA8 6SA8 = SHORT: KAIROSNAME: SA8
4SA9 4SA23 5SA9 5SA23 6SA9 6SA23 = SHORT: KAIROSNAME: SA9
4SA10 4SA24 5SA10 5SA24 6SA10 6SA24 = SHORT: KAIROSNAME: SA10
4TP_DPS1 5TP_DPS1 6TP_DPS1 = TP01: KAIROSNAME: TP_DPS1
4TP_DPS2 5TP_DPS2 6TP_DPS2 = TP01: KAIROSNAME: S1_DPS3
4TP_DPS3 4TP_DPS4 4TP_DPS9 5TP_DPS3 5TP_DPS4 5TP_DPS9 6TP_DPS3 6TP_DPS4 6TP_DPS9 = TP01: KAIROSNAME: S1_DPS4
4TP_DPS5 5TP_DPS5 6TP_DPS5 = TP01: KAIROSNAME: S1_DPS5
4TP_DPS6 5TP_DPS6 6TP_DPS6 = TP01: KAIROSNAME: TP_DPS8
4TP_DPS7 4TP_DPS8 5TP_DPS7 5TP_DPS8 6TP_DPS7 6TP_DPS8 = TP01: KAIROSNAME: TP_DPS2
SITE4-SITE6 = I6K51D-BGA290-9X7
4BDB5 4BDB8 5BDB5 5BDB8 = BD120-1.5A-S4-MU: KAIROSNAME: BDB5
4BDB6 4BDB7 5BDB6 5BDB7 = BD120-1.5A-S4-MU: KAIROSNAME: BDB6
4C302 4C318 4C1088 4C1093 5C302 5C318 5C1088 5C1093 = 10P-50-N-S2-MU: KAIROSNAME: C318
4C309 4C1086 5C309 5C1086 = 10P-50-N-S2-MU: KAIROSNAME: C309
4C310 4C1087 5C310 5C1087 = 10P-50-N-S2-MU: KAIROSNAME: C310
4C320 4C1091 5C320 5C1091 = 10P-50-N-S2-MU: KAIROSNAME: C320
4C922 4C1090 5C922 5C1090 = 0.1U-16-X-S4-MU: KAIROSNAME: C922
4C923 4C1089 5C923 5C1089 = 0.1U-16-X-S4-MU: KAIROSNAME: C923
4C924 5C924 = 10P-50-N-S2-MU: KAIROSNAME: C924
4R168 4R1099 5R168 5R1099 = 42.2-1-S2: KAIROSNAME: R168
4R170 4R1100 5R170 5R1100 = 42.2-1-S2: KAIROSNAME: R170
4R172 4R1104 5R172 5R1104 = 0-5-S2: KAIROSNAME: R172
4R176 4R1089 4R1106 4R1115 5R176 5R1089 5R1106 5R1115 = 42.2-1-S2: KAIROSNAME: R176
4R178 4R1088 4R1103 4R1114 5R178 5R1088 5R1103 5R1114 = 42.2-1-S2: KAIROSNAME: R178
4R180 4R1110 5R180 5R1110 = 42.2-1-S2: KAIROSNAME: R180
4R182 4R1111 5R182 5R1111 = 42.2-1-S2: KAIROSNAME: R182
4R234 4R1117-4R1119 5R234 5R1117-5R1119 = 0-1-S4-YA
4R646 4R1107 5R646 5R1107 = 42.2-1-S2: KAIROSNAME: R646
4R647 4R1109 5R647 5R1109 = 42.2-1-S2: KAIROSNAME: R647
4R659 4R1105 5R659 5R1105 = 10K-1-S2-WA: KAIROSNAME: R659
4R661 4R1101 5R661 5R1101 = 4.7K-1-S2: KAIROSNAME: R661
4R662 4R1102 5R662 5R1102 = 0-5-S2: KAIROSNAME: R662
4R663 4R1098 5R663 5R1098 = 4.7K-1-S2: KAIROSNAME: R663
4R664 5R664 = 42.2-1-S2: KAIROSNAME: R664
4R666 5R666 = 42.2-1-S2: KAIROSNAME: R666
4R672 4R1108 5R672 5R1108 = 10K-1-S2-WA: KAIROSNAME: R672
4U408 4U455 5U408 5U455 = CBTL06GP213EE-TFBGA50: KAIROSNAME: U408
4U409 4U456 5U409 5U456 = CBTL06GP213EE-TFBGA50: KAIROSNAME: U409

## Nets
DGND: 4C302.2 4C309.2 4C310.2 4C318.2 4C320.2 4C922.1 4C923.1 4C924.2 4C1086.2 4C1087.2 4C1088.2 4C1089.1 4C1090.1 4C1091.2 4C1093.2 4CA1.2 4CA2.2 4CA7.2 4CA8.2 4CA19.2 4CA20.2 4CA21.2 4CA22.2 4CA23.2 4CA24.2 4CA25.2 4CA26.2 4CA27.2 4CA34.2 4CA35.2 4CA36.2 4CA37.2 4CA38.2 4CA39.2 4CC1.2 4CC2.2 4CC3.2 4CC4.2 4CC5.2 4CC6.2 4CC7.2 4CC8.2 4CC9.2 4CC12.2 4CC13.2 4CC14.2 4CC15.2 4CC16.2 4CC70.2 4CC71.2 4CC73.2 4CC84.2 4CC85.2 4CC86.2 4CC87.2 4CC88.2 4CC89.2 4CC90.2 4CC91.2 4CC92.2 4CC96.2 4CC101.2 4CC103.2 4CC105.2 4CC112.2 4CC130.2 4CC182.2 4CC195.2 4CC202.2 4CC211.2 4CC212.2 4CC213.2 4CC214.2 4CC215.2 4CC216.2 4CC217.2 4CC218.2 4CC219.2 4CC220.2 4R659.2 4R672.2 4R1105.2 4R1108.2 4SA2.1 4SA7.1 4SA10.1 4SA15.1 4SA18.1 4SA20.1 4SA22.1 4SA24.1 4SA26.1 4U408.B3(GND) 4U408.C8(GND) 4U408.G2(GND) 4U408.G8(GND) 4U408.H4(GND) 4U408.H7(GND) 4U409.B3(GND) 4U409.C8(GND) 4U409.G2(GND) 4U409.G8(GND) 4U409.H4(GND) 4U409.H7(GND) 4U455.B3(GND) 4U455.C8(GND) 4U455.G2(GND) 4U455.G8(GND) 4U455.H4(GND) 4U455.H7(GND) 4U456.B3(GND) 4U456.C8(GND) 4U456.G2(GND) 4U456.G8(GND) 4U456.H4(GND) 4U456.H7(GND) 5C302.2 5C309.2 5C310.2 5C318.2 5C320.2 5C922.1 5C923.1 5C924.2 5C1086.2 5C1087.2 5C1088.2 5C1089.1 5C1090.1 5C1091.2 5C1093.2 5CA1.2 5CA2.2 5CA7.2 5CA8.2 5CA19.2 5CA20.2 5CA21.2 5CA22.2 5CA23.2 5CA24.2 5CA25.2 5CA26.2 5CA27.2 5CA34.2 5CA35.2 5CA36.2 5CA37.2 5CA38.2 5CA39.2 5CC1.2 5CC2.2 5CC3.2 5CC4.2 5CC5.2 5CC6.2 5CC7.2 5CC8.2 5CC9.2 5CC12.2 5CC13.2 5CC14.2 5CC15.2 5CC16.2 5CC70.2 5CC71.2 5CC73.2 5CC84.2 5CC85.2 5CC86.2 5CC87.2 5CC88.2 5CC89.2 5CC90.2 5CC91.2 5CC92.2 5CC96.2 5CC101.2 5CC103.2 5CC105.2 5CC112.2 5CC130.2 5CC182.2 5CC195.2 5CC202.2 5CC211.2 5CC212.2 5CC213.2 5CC214.2 5CC215.2 5CC216.2 5CC217.2 5CC218.2 5CC219.2 5CC220.2 5R659.2 5R672.2 5R1105.2 5R1108.2 5SA2.1 5SA7.1 5SA10.1 5SA15.1 5SA18.1 5SA20.1 5SA22.1 5SA24.1 5SA26.1 5U408.B3(GND) 5U408.C8(GND) 5U408.G2(GND) 5U408.G8(GND) 5U408.H4(GND) 5U408.H7(GND) 5U409.B3(GND) 5U409.C8(GND) 5U409.G2(GND) 5U409.G8(GND) 5U409.H4(GND) 5U409.H7(GND) 5U455.B3(GND) 5U455.C8(GND) 5U455.G2(GND) 5U455.G8(GND) 5U455.H4(GND) 5U455.H7(GND) 5U456.B3(GND) 5U456.C8(GND) 5U456.G2(GND) 5U456.G8(GND) 5U456.H4(GND) 5U456.H7(GND) 6CA1.2 6CA2.2 6CA7.2 6CA8.2 6CA19.2 6CA20.2 6CA21.2 6CA22.2 6CA23.2 6CA24.2 6CA25.2 6CA26.2 6CA27.2 6CA34.2 6CA35.2 6CA36.2 6CA37.2 6CA38.2 6CA39.2 6CC1.2 6CC2.2 6CC3.2 6CC4.2 6CC5.2 6CC6.2 6CC7.2 6CC8.2 6CC9.2 6CC12.2 6CC13.2 6CC14.2 6CC15.2 6CC16.2 6CC70.2 6CC71.2 6CC73.2 6CC84.2 6CC85.2 6CC86.2 6CC87.2 6CC88.2 6CC89.2 6CC90.2 6CC91.2 6CC92.2 6CC96.2 6CC101.2 6CC103.2 6CC105.2 6CC112.2 6CC130.2 6CC182.2 6CC195.2 6CC202.2 6CC211.2 6CC212.2 6CC213.2 6CC214.2 6CC215.2 6CC216.2 6CC217.2 6CC218.2 6CC219.2 6CC220.2 6SA2.1 6SA7.1 6SA10.1 6SA15.1 6SA18.1 6SA20.1 6SA22.1 6SA24.1 6SA26.1 ; also on sheet 1 2 3 4 5 11 12 13 14 17 18 19 20 21 22 23 24 25 26 27 28 30 31 32 33 34 35 36 37
4SA_CBIT_R96: 4K96.12(V-)
4SA_CBIT_S20: 4R662.2 4R1102.2
4SA_CBIT_S29: 4R172.2 4R1104.2
5SA_CBIT_R96: 5K96.12(V-)
5SA_CBIT_S20: 5R662.2 5R1102.2
5SA_CBIT_S29: 5R172.2 5R1104.2
6SA_CBIT_R96: 6K96.12(V-)
S4_3V3_RX0_MIPI: 4BDB5.2 4C922.2 4R661.2 4U408.A2(VDD) 4U408.J4(VDD)
S4_3V3_RX1_MIPI: 4BDB6.2 4C923.2 4R663.2 4U409.A2(VDD) 4U409.J4(VDD)
S4_3V3_TX0_MIPI: 4BDB8.2 4C1090.2 4R1101.2 4U455.A2(VDD) 4U455.J4(VDD)
S4_3V3_TX1_MIPI: 4BDB7.2 4C1089.2 4R1098.2 4U456.A2(VDD) 4U456.J4(VDD)
S4_B_DCH001: 4CC195.1 SITE4.M18(VDDP18_LDO_P0)
S4_DPS3: 4CA20.1 4CA21.1 4CC84.1 4CC85.1 4CC86.1 4CC87.1 4CC88.1 4CC89.1 4CC90.1 4CC91.1 4CC92.1 4SA17.1 4TP_DPS3.1(TP) SITE4.F4(VDDP18_P1) SITE4.F17(AVDD18_NODIE) SITE4.G5(AVDD18_MIPI_TX) SITE4.H4(AVDD18_USB) SITE4.J18(AVDD18_OTP) SITE4.L5(AVDD18_AUD) SITE4.R11(AVDD18_PLL_DDR) SITE4.R14(VDD1_DRAM[0]) SITE4.R15(VDD1_DRAM[1])
S4_DPS4: 4CA34.1 4CA35.1 4CC182.1 4CC202.1 4SA19.1 4TP_DPS4.1(TP) SITE4.H19(AVDD33_ETH) SITE4.J5(AVDD33_USB)
S4_Mpdch37+: 4U408.B8(DIN2_0+)
S4_Mpdch37-: 4U408.B9(DIN2_0-)
S4_Mpdch38+: 4U455.B8(DIN2_0+)
S4_Mpdch38-: 4U455.B9(DIN2_0-)
S4_Mpdch39+: 4U408.D8(DIN2_1+)
S4_Mpdch39-: 4U408.D9(DIN2_1-)
S4_Mpdch40+: 4U455.D8(DIN2_1+)
S4_Mpdch40-: 4U455.D9(DIN2_1-)
S4_Mpdch41+: 4U408.E8(DIN2_2+)
S4_Mpdch41-: 4U408.E9(DIN2_2-)
S4_Mpdch42+: 4U455.E8(DIN2_2+)
S4_Mpdch42-: 4U455.E9(DIN2_2-)
S4_Mpdch43+: 4U409.B8(DIN2_0+)
S4_Mpdch43-: 4U409.B9(DIN2_0-)
S4_Mpdch44+: 4U456.B8(DIN2_0+)
S4_Mpdch44-: 4U456.B9(DIN2_0-)
S4_Mpdch45+: 4U409.D8(DIN2_1+)
S4_Mpdch45-: 4U409.D9(DIN2_1-)
S4_Mpdch46+: 4U456.D8(DIN2_1+)
S4_Mpdch46-: 4U456.D9(DIN2_1-)
S4_Mpdch47+: 4U409.E8(DIN2_2+)
S4_Mpdch47-: 4U409.E9(DIN2_2-)
S4_MUX_3V3: 4R234.2 4R1117.2 4R1118.2 4R1119.2 ; also on sheet 34
S4_OUT_RX0_CH0_ABC_CASE+: 4U408.B2(DOUT_0+) SITE4.B10(PAD_OUTP_RX0_CH[0])
S4_OUT_RX0_CH0_ABC_CASE-: 4U408.B1(DOUT_0-) SITE4.A10(PAD_OUTN_RX0_CH[0])
S4_OUT_RX0_CH0_B_CASE+: 4R647.1 4U408.B4(DIN1_0+)
S4_OUT_RX0_CH0_B_CASE-: 4R646.1 4U408.A4(DIN1_0-)
S4_OUT_RX0_CH0_C_CASE: 4C309.1 4R646.2 4R647.2
S4_OUT_RX0_CH1_ABC_CASE+: 4U408.D2(DOUT_1+) SITE4.B9(PAD_OUTP_RX0_CH[1])
S4_OUT_RX0_CH1_ABC_CASE-: 4U408.D1(DOUT_1-) SITE4.B8(PAD_OUTN_RX0_CH[1])
S4_OUT_RX0_CH1_B_CASE+: 4R168.1 4U408.B5(DIN1_1+)
S4_OUT_RX0_CH1_B_CASE-: 4R170.1 4U408.A5(DIN1_1-)
S4_OUT_RX0_CH1_C_CASE: 4C310.1 4R168.2 4R170.2
S4_OUT_RX0_CH2_ABC_CASE+: 4U408.E2(DOUT_2+) SITE4.A8(PAD_OUTP_RX0_CH[2])
S4_OUT_RX0_CH2_ABC_CASE-: 4U408.E1(DOUT_2-) SITE4.B7(PAD_OUTN_RX0_CH[2])
S4_OUT_RX0_CH2_B_CASE+: 4R176.1 4U408.B6(DIN1_2+)
S4_OUT_RX0_CH2_B_CASE-: 4R178.1 4U408.A6(DIN1_2-)
S4_OUT_RX0_CH2_C_CASE: 4C318.1 4R176.2 4R178.2
S4_OUT_RX0_CH3_ABC_CASE+: 4U409.B2(DOUT_0+) SITE4.B6(PAD_OUTP_RX0_CH[3])
S4_OUT_RX0_CH3_ABC_CASE-: 4U409.B1(DOUT_0-) SITE4.A6(PAD_OUTN_RX0_CH[3])
S4_OUT_RX0_CH3_B_CASE+: 4R1089.1 4U409.B4(DIN1_0+)
S4_OUT_RX0_CH3_B_CASE-: 4R1088.1 4U409.A4(DIN1_0-)
S4_OUT_RX0_CH3_C_CASE: 4C302.1 4R1088.2 4R1089.2
S4_OUT_RX0_CH4_ABC_CASE+: 4U409.D2(DOUT_1+) SITE4.B5(PAD_OUTP_RX0_CH[4])
S4_OUT_RX0_CH4_ABC_CASE-: 4U409.D1(DOUT_1-) SITE4.B4(PAD_OUTN_RX0_CH[4])
S4_OUT_RX0_CH4_B_CASE+: 4R180.1 4U409.B5(DIN1_1+)
S4_OUT_RX0_CH4_B_CASE-: 4R182.1 4U409.A5(DIN1_1-)
S4_OUT_RX0_CH4_C_CASE: 4C320.1 4R180.2 4R182.2
S4_OUT_RX0_CH5_ABC_CASE+: 4U409.E2(DOUT_2+) SITE4.A4(PAD_OUTP_RX0_CH[5])
S4_OUT_RX0_CH5_ABC_CASE-: 4U409.E1(DOUT_2-) SITE4.B3(PAD_OUTN_RX0_CH[5])
S4_OUT_RX0_CH5_B_CASE+: 4R666.1 4U409.B6(DIN1_2+)
S4_OUT_RX0_CH5_B_CASE-: 4R664.1 4U409.A6(DIN1_2-)
S4_OUT_RX0_CH5_C_CASE: 4C924.1 4R664.2 4R666.2
S4_OUT_TX0_CH0_ABC_CASE+: 4U455.B2(DOUT_0+) SITE4.A2(PAD_OUTP_TX0_CH[0])
S4_OUT_TX0_CH0_ABC_CASE-: 4U455.B1(DOUT_0-) SITE4.B1(PAD_OUTN_TX0_CH[0])
S4_OUT_TX0_CH0_B_CASE+: 4R1109.1 4U455.B4(DIN1_0+)
S4_OUT_TX0_CH0_B_CASE-: 4R1107.1 4U455.A4(DIN1_0-)
S4_OUT_TX0_CH0_C_CASE: 4C1086.1 4R1107.2 4R1109.2
S4_OUT_TX0_CH1_ABC_CASE+: 4U455.D2(DOUT_1+) SITE4.C1(PAD_OUTP_TX0_CH[1])
S4_OUT_TX0_CH1_ABC_CASE-: 4U455.D1(DOUT_1-) SITE4.C2(PAD_OUTN_TX0_CH[1])
S4_OUT_TX0_CH1_B_CASE+: 4R1099.1 4U455.B5(DIN1_1+)
S4_OUT_TX0_CH1_B_CASE-: 4R1100.1 4U455.A5(DIN1_1-)
S4_OUT_TX0_CH1_C_CASE: 4C1087.1 4R1099.2 4R1100.2
S4_OUT_TX0_CH2_ABC_CASE+: 4U455.E2(DOUT_2+) SITE4.D2(PAD_OUTP_TX0_CH[2])
S4_OUT_TX0_CH2_ABC_CASE-: 4U455.E1(DOUT_2-) SITE4.E1(PAD_OUTN_TX0_CH[2])
S4_OUT_TX0_CH2_B_CASE+: 4R1106.1 4U455.B6(DIN1_2+)
S4_OUT_TX0_CH2_B_CASE-: 4R1103.1 4U455.A6(DIN1_2-)
S4_OUT_TX0_CH2_C_CASE: 4C1088.1 4R1103.2 4R1106.2
S4_OUT_TX0_CH3_ABC_CASE+: 4U456.B2(DOUT_0+) SITE4.E2(PAD_OUTP_TX0_CH[3])
S4_OUT_TX0_CH3_ABC_CASE-: 4U456.B1(DOUT_0-) SITE4.F2(PAD_OUTN_TX0_CH[3])
S4_OUT_TX0_CH3_B_CASE+: 4R1115.1 4U456.B4(DIN1_0+)
S4_OUT_TX0_CH3_B_CASE-: 4R1114.1 4U456.A4(DIN1_0-)
S4_OUT_TX0_CH3_C_CASE: 4C1093.1 4R1114.2 4R1115.2
S4_OUT_TX0_CH4_ABC_CASE+: 4U456.D2(DOUT_1+) SITE4.G1(PAD_OUTP_TX0_CH[4])
S4_OUT_TX0_CH4_ABC_CASE-: 4U456.D1(DOUT_1-) SITE4.G2(PAD_OUTN_TX0_CH[4])
S4_OUT_TX0_CH4_B_CASE+: 4R1110.1 4U456.B5(DIN1_1+)
S4_OUT_TX0_CH4_B_CASE-: 4R1111.1 4U456.A5(DIN1_1-)
S4_OUT_TX0_CH4_C_CASE: 4C1091.1 4R1110.2 4R1111.2
S4_PWR_F001: 4CA26.1 4CA27.1 4CC112.1 4SA16.1 4TP_DPS2.1(TP) SITE4.F15(DVDD_NODIE)
S4_PWR_F004: 4CA22.1 4CA23.1 4CC96.1 4SA21.1 4TP_DPS5.1(TP) SITE4.E10(AVDD33_RTC)
S4_PWR_F005: 4CA7.1 4CA8.1 4CC70.1 4CC71.1 4CC73.1 4SA8.1 4TP_DPS6.1(TP) SITE4.G18(VDDP3318_PM) SITE4.N17(VDDP3318_P0) SITE4.P3(VDDP3318_P2)
S4_PWR_F006: 4CA24.1 4CA25.1 4CC101.1 4CC103.1 4CC105.1 4SA9.1 4TP_DPS7.1(TP) SITE4.T13(VDD2_DRAM[0]) SITE4.T14(VDD2_DRAM[1]) SITE4.U13(VDD2_DRAM[2])
S4_PWR_F007: 4CA36.1 4CA37.1 4CC211.1 4CC212.1 4CC213.1 4SA23.1 4TP_DPS8.1(TP) SITE4.T10(VDDQ_DRAM[0]) SITE4.T11(VDDQ_DRAM[1]) SITE4.U11(VDDQ_DRAM[2])
S4_PWR_F008: 4CA38.1 4CA39.1 4CC220.1 4SA25.1 4TP_DPS9.1(TP) SITE4.K19(AVDD18_XTAL)
S4_PWR_GS001: 4SA15.2
S4_PWR_GS002: 4SA18.2
S4_PWR_GS003: 4SA20.2
S4_PWR_GS004: 4SA22.2
S4_PWR_GS005: 4SA7.2
S4_PWR_GS006: 4SA10.2
S4_PWR_GS007: 4SA24.2
S4_PWR_GS008: 4SA26.2
S4_PWR_M_F001: 4CA1.1 4CA2.1 4CC1.1 4CC2.1 4CC3.1 4CC4.1 4CC5.1 4CC6.1 4CC7.1 4CC8.1 4CC9.1 4CC12.1 4CC13.1 4CC14.1 4CC15.1 4CC16.1 4CC130.1 4CC214.1 4CC215.1 4CC216.1 4CC217.1 4CC218.1 4CC219.1 4K96.4 4K96.9 4SA1.1 4TP_DPS1.1(TP) SITE4.F6(AVDDL_MIPI_RX) SITE4.F7(VDD_CPU[0]) SITE4.F8(VDD_CPU[1]) SITE4.G6(AVDDL_MIPI_TX) SITE4.G7(VDD_CPU[2]) SITE4.G8(VDD_CPU[3]) SITE4.G10(VDD[0]) SITE4.G11(VDD[1]) SITE4.H7(VDD_CPU[4]) SITE4.H8(VDD_CPU[5]) SITE4.H10(VDD[2]) SITE4.H11(VDD[3]) SITE4.H12(VDD[4]) SITE4.J10(VDD[5]) SITE4.J11(VDD[6]) SITE4.J12(VDD[7]) SITE4.J13(VDD[8]) SITE4.K10(VDD[9]) SITE4.K11(VDD[10]) SITE4.K12(VDD[11]) SITE4.K13(VDD[12])
S4_PWR_M_GS001: 4SA2.2
S4_PWR_M_S001: 4SA1.2
S4_PWR_S001: 4SA16.2
S4_PWR_S002: 4SA17.2
S4_PWR_S003: 4SA19.2
S4_PWR_S004: 4SA21.2
S4_PWR_S005: 4SA8.2
S4_PWR_S006: 4SA9.2
S4_PWR_S007: 4SA23.2
S4_PWR_S008: 4SA25.2
S5_3V3_RX0_MIPI: 5BDB5.2 5C922.2 5R661.2 5U408.A2(VDD) 5U408.J4(VDD)
S5_3V3_RX1_MIPI: 5BDB6.2 5C923.2 5R663.2 5U409.A2(VDD) 5U409.J4(VDD)
S5_3V3_TX0_MIPI: 5BDB8.2 5C1090.2 5R1101.2 5U455.A2(VDD) 5U455.J4(VDD)
S5_3V3_TX1_MIPI: 5BDB7.2 5C1089.2 5R1098.2 5U456.A2(VDD) 5U456.J4(VDD)
S5_B_DCH001: 5CC195.1 SITE5.M18(VDDP18_LDO_P0)
S5_DPS3: 5CA20.1 5CA21.1 5CC84.1 5CC85.1 5CC86.1 5CC87.1 5CC88.1 5CC89.1 5CC90.1 5CC91.1 5CC92.1 5SA17.1 5TP_DPS3.1(TP) SITE5.F4(VDDP18_P1) SITE5.F17(AVDD18_NODIE) SITE5.G5(AVDD18_MIPI_TX) SITE5.H4(AVDD18_USB) SITE5.J18(AVDD18_OTP) SITE5.L5(AVDD18_AUD) SITE5.R11(AVDD18_PLL_DDR) SITE5.R14(VDD1_DRAM[0]) SITE5.R15(VDD1_DRAM[1])
S5_DPS4: 5CA34.1 5CA35.1 5CC182.1 5CC202.1 5SA19.1 5TP_DPS4.1(TP) SITE5.H19(AVDD33_ETH) SITE5.J5(AVDD33_USB)
S5_Mpdch37+: 5U408.B8(DIN2_0+)
S5_Mpdch37-: 5U408.B9(DIN2_0-)
S5_Mpdch38+: 5U455.B8(DIN2_0+)
S5_Mpdch38-: 5U455.B9(DIN2_0-)
S5_Mpdch39+: 5U408.D8(DIN2_1+)
S5_Mpdch39-: 5U408.D9(DIN2_1-)
S5_Mpdch40+: 5U455.D8(DIN2_1+)
S5_Mpdch40-: 5U455.D9(DIN2_1-)
S5_Mpdch41+: 5U408.E8(DIN2_2+)
S5_Mpdch41-: 5U408.E9(DIN2_2-)
S5_Mpdch42+: 5U455.E8(DIN2_2+)
S5_Mpdch42-: 5U455.E9(DIN2_2-)
S5_Mpdch43+: 5U409.B8(DIN2_0+)
S5_Mpdch43-: 5U409.B9(DIN2_0-)
S5_Mpdch44+: 5U456.B8(DIN2_0+)
S5_Mpdch44-: 5U456.B9(DIN2_0-)
S5_Mpdch45+: 5U409.D8(DIN2_1+)
S5_Mpdch45-: 5U409.D9(DIN2_1-)
S5_Mpdch46+: 5U456.D8(DIN2_1+)
S5_Mpdch46-: 5U456.D9(DIN2_1-)
S5_Mpdch47+: 5U409.E8(DIN2_2+)
S5_Mpdch47-: 5U409.E9(DIN2_2-)
S5_MUX_3V3: 5R234.2 5R1117.2 5R1118.2 5R1119.2 ; also on sheet 33
S5_OUT_RX0_CH0_ABC_CASE+: 5U408.B2(DOUT_0+) SITE5.B10(PAD_OUTP_RX0_CH[0])
S5_OUT_RX0_CH0_ABC_CASE-: 5U408.B1(DOUT_0-) SITE5.A10(PAD_OUTN_RX0_CH[0])
S5_OUT_RX0_CH0_B_CASE+: 5R647.1 5U408.B4(DIN1_0+)
S5_OUT_RX0_CH0_B_CASE-: 5R646.1 5U408.A4(DIN1_0-)
S5_OUT_RX0_CH0_C_CASE: 5C309.1 5R646.2 5R647.2
S5_OUT_RX0_CH1_ABC_CASE+: 5U408.D2(DOUT_1+) SITE5.B9(PAD_OUTP_RX0_CH[1])
S5_OUT_RX0_CH1_ABC_CASE-: 5U408.D1(DOUT_1-) SITE5.B8(PAD_OUTN_RX0_CH[1])
S5_OUT_RX0_CH1_B_CASE+: 5R168.1 5U408.B5(DIN1_1+)
S5_OUT_RX0_CH1_B_CASE-: 5R170.1 5U408.A5(DIN1_1-)
S5_OUT_RX0_CH1_C_CASE: 5C310.1 5R168.2 5R170.2
S5_OUT_RX0_CH2_ABC_CASE+: 5U408.E2(DOUT_2+) SITE5.A8(PAD_OUTP_RX0_CH[2])
S5_OUT_RX0_CH2_ABC_CASE-: 5U408.E1(DOUT_2-) SITE5.B7(PAD_OUTN_RX0_CH[2])
S5_OUT_RX0_CH2_B_CASE+: 5R176.1 5U408.B6(DIN1_2+)
S5_OUT_RX0_CH2_B_CASE-: 5R178.1 5U408.A6(DIN1_2-)
S5_OUT_RX0_CH2_C_CASE: 5C318.1 5R176.2 5R178.2
S5_OUT_RX0_CH3_ABC_CASE+: 5U409.B2(DOUT_0+) SITE5.B6(PAD_OUTP_RX0_CH[3])
S5_OUT_RX0_CH3_ABC_CASE-: 5U409.B1(DOUT_0-) SITE5.A6(PAD_OUTN_RX0_CH[3])
S5_OUT_RX0_CH3_B_CASE+: 5R1089.1 5U409.B4(DIN1_0+)
S5_OUT_RX0_CH3_B_CASE-: 5R1088.1 5U409.A4(DIN1_0-)
S5_OUT_RX0_CH3_C_CASE: 5C302.1 5R1088.2 5R1089.2
S5_OUT_RX0_CH4_ABC_CASE+: 5U409.D2(DOUT_1+) SITE5.B5(PAD_OUTP_RX0_CH[4])
S5_OUT_RX0_CH4_ABC_CASE-: 5U409.D1(DOUT_1-) SITE5.B4(PAD_OUTN_RX0_CH[4])
S5_OUT_RX0_CH4_B_CASE+: 5R180.1 5U409.B5(DIN1_1+)
S5_OUT_RX0_CH4_B_CASE-: 5R182.1 5U409.A5(DIN1_1-)
S5_OUT_RX0_CH4_C_CASE: 5C320.1 5R180.2 5R182.2
S5_OUT_RX0_CH5_ABC_CASE+: 5U409.E2(DOUT_2+) SITE5.A4(PAD_OUTP_RX0_CH[5])
S5_OUT_RX0_CH5_ABC_CASE-: 5U409.E1(DOUT_2-) SITE5.B3(PAD_OUTN_RX0_CH[5])
S5_OUT_RX0_CH5_B_CASE+: 5R666.1 5U409.B6(DIN1_2+)
S5_OUT_RX0_CH5_B_CASE-: 5R664.1 5U409.A6(DIN1_2-)
S5_OUT_RX0_CH5_C_CASE: 5C924.1 5R664.2 5R666.2
S5_OUT_TX0_CH0_ABC_CASE+: 5U455.B2(DOUT_0+) SITE5.A2(PAD_OUTP_TX0_CH[0])
S5_OUT_TX0_CH0_ABC_CASE-: 5U455.B1(DOUT_0-) SITE5.B1(PAD_OUTN_TX0_CH[0])
S5_OUT_TX0_CH0_B_CASE+: 5R1109.1 5U455.B4(DIN1_0+)
S5_OUT_TX0_CH0_B_CASE-: 5R1107.1 5U455.A4(DIN1_0-)
S5_OUT_TX0_CH0_C_CASE: 5C1086.1 5R1107.2 5R1109.2
S5_OUT_TX0_CH1_ABC_CASE+: 5U455.D2(DOUT_1+) SITE5.C1(PAD_OUTP_TX0_CH[1])
S5_OUT_TX0_CH1_ABC_CASE-: 5U455.D1(DOUT_1-) SITE5.C2(PAD_OUTN_TX0_CH[1])
S5_OUT_TX0_CH1_B_CASE+: 5R1099.1 5U455.B5(DIN1_1+)
S5_OUT_TX0_CH1_B_CASE-: 5R1100.1 5U455.A5(DIN1_1-)
S5_OUT_TX0_CH1_C_CASE: 5C1087.1 5R1099.2 5R1100.2
S5_OUT_TX0_CH2_ABC_CASE+: 5U455.E2(DOUT_2+) SITE5.D2(PAD_OUTP_TX0_CH[2])
S5_OUT_TX0_CH2_ABC_CASE-: 5U455.E1(DOUT_2-) SITE5.E1(PAD_OUTN_TX0_CH[2])
S5_OUT_TX0_CH2_B_CASE+: 5R1106.1 5U455.B6(DIN1_2+)
S5_OUT_TX0_CH2_B_CASE-: 5R1103.1 5U455.A6(DIN1_2-)
S5_OUT_TX0_CH2_C_CASE: 5C1088.1 5R1103.2 5R1106.2
S5_OUT_TX0_CH3_ABC_CASE+: 5U456.B2(DOUT_0+) SITE5.E2(PAD_OUTP_TX0_CH[3])
S5_OUT_TX0_CH3_ABC_CASE-: 5U456.B1(DOUT_0-) SITE5.F2(PAD_OUTN_TX0_CH[3])
S5_OUT_TX0_CH3_B_CASE+: 5R1115.1 5U456.B4(DIN1_0+)
S5_OUT_TX0_CH3_B_CASE-: 5R1114.1 5U456.A4(DIN1_0-)
S5_OUT_TX0_CH3_C_CASE: 5C1093.1 5R1114.2 5R1115.2
S5_OUT_TX0_CH4_ABC_CASE+: 5U456.D2(DOUT_1+) SITE5.G1(PAD_OUTP_TX0_CH[4])
S5_OUT_TX0_CH4_ABC_CASE-: 5U456.D1(DOUT_1-) SITE5.G2(PAD_OUTN_TX0_CH[4])
S5_OUT_TX0_CH4_B_CASE+: 5R1110.1 5U456.B5(DIN1_1+)
S5_OUT_TX0_CH4_B_CASE-: 5R1111.1 5U456.A5(DIN1_1-)
S5_OUT_TX0_CH4_C_CASE: 5C1091.1 5R1110.2 5R1111.2
S5_PWR_F001: 5CA26.1 5CA27.1 5CC112.1 5SA16.1 5TP_DPS2.1(TP) SITE5.F15(DVDD_NODIE)
S5_PWR_F004: 5CA22.1 5CA23.1 5CC96.1 5SA21.1 5TP_DPS5.1(TP) SITE5.E10(AVDD33_RTC)
S5_PWR_F005: 5CA7.1 5CA8.1 5CC70.1 5CC71.1 5CC73.1 5SA8.1 5TP_DPS6.1(TP) SITE5.G18(VDDP3318_PM) SITE5.N17(VDDP3318_P0) SITE5.P3(VDDP3318_P2)
S5_PWR_F006: 5CA24.1 5CA25.1 5CC101.1 5CC103.1 5CC105.1 5SA9.1 5TP_DPS7.1(TP) SITE5.T13(VDD2_DRAM[0]) SITE5.T14(VDD2_DRAM[1]) SITE5.U13(VDD2_DRAM[2])
S5_PWR_F007: 5CA36.1 5CA37.1 5CC211.1 5CC212.1 5CC213.1 5SA23.1 5TP_DPS8.1(TP) SITE5.T10(VDDQ_DRAM[0]) SITE5.T11(VDDQ_DRAM[1]) SITE5.U11(VDDQ_DRAM[2])
S5_PWR_F008: 5CA38.1 5CA39.1 5CC220.1 5SA25.1 5TP_DPS9.1(TP) SITE5.K19(AVDD18_XTAL)
S5_PWR_GS001: 5SA15.2
S5_PWR_GS002: 5SA18.2
S5_PWR_GS003: 5SA20.2
S5_PWR_GS004: 5SA22.2
S5_PWR_GS005: 5SA7.2
S5_PWR_GS006: 5SA10.2
S5_PWR_GS007: 5SA24.2
S5_PWR_GS008: 5SA26.2
S5_PWR_M_F001: 5CA1.1 5CA2.1 5CC1.1 5CC2.1 5CC3.1 5CC4.1 5CC5.1 5CC6.1 5CC7.1 5CC8.1 5CC9.1 5CC12.1 5CC13.1 5CC14.1 5CC15.1 5CC16.1 5CC130.1 5CC214.1 5CC215.1 5CC216.1 5CC217.1 5CC218.1 5CC219.1 5K96.4 5K96.9 5SA1.1 5TP_DPS1.1(TP) SITE5.F6(AVDDL_MIPI_RX) SITE5.F7(VDD_CPU[0]) SITE5.F8(VDD_CPU[1]) SITE5.G6(AVDDL_MIPI_TX) SITE5.G7(VDD_CPU[2]) SITE5.G8(VDD_CPU[3]) SITE5.G10(VDD[0]) SITE5.G11(VDD[1]) SITE5.H7(VDD_CPU[4]) SITE5.H8(VDD_CPU[5]) SITE5.H10(VDD[2]) SITE5.H11(VDD[3]) SITE5.H12(VDD[4]) SITE5.J10(VDD[5]) SITE5.J11(VDD[6]) SITE5.J12(VDD[7]) SITE5.J13(VDD[8]) SITE5.K10(VDD[9]) SITE5.K11(VDD[10]) SITE5.K12(VDD[11]) SITE5.K13(VDD[12])
S5_PWR_M_GS001: 5SA2.2
S5_PWR_M_S001: 5SA1.2
S5_PWR_S001: 5SA16.2
S5_PWR_S002: 5SA17.2
S5_PWR_S003: 5SA19.2
S5_PWR_S004: 5SA21.2
S5_PWR_S005: 5SA8.2
S5_PWR_S006: 5SA9.2
S5_PWR_S007: 5SA23.2
S5_PWR_S008: 5SA25.2
S6_B_DCH001: 6CC195.1 SITE6.M18(VDDP18_LDO_P0)
S6_DPS3: 6CA20.1 6CA21.1 6CC84.1 6CC85.1 6CC86.1 6CC87.1 6CC88.1 6CC89.1 6CC90.1 6CC91.1 6CC92.1 6SA17.1 6TP_DPS3.1(TP) SITE6.F4(VDDP18_P1) SITE6.F17(AVDD18_NODIE) SITE6.G5(AVDD18_MIPI_TX) SITE6.H4(AVDD18_USB) SITE6.J18(AVDD18_OTP) SITE6.L5(AVDD18_AUD) SITE6.R11(AVDD18_PLL_DDR) SITE6.R14(VDD1_DRAM[0]) SITE6.R15(VDD1_DRAM[1])
S6_DPS4: 6CA34.1 6CA35.1 6CC182.1 6CC202.1 6SA19.1 6TP_DPS4.1(TP) SITE6.H19(AVDD33_ETH) SITE6.J5(AVDD33_USB)
S6_PWR_F001: 6CA26.1 6CA27.1 6CC112.1 6SA16.1 6TP_DPS2.1(TP) SITE6.F15(DVDD_NODIE)
S6_PWR_F004: 6CA22.1 6CA23.1 6CC96.1 6SA21.1 6TP_DPS5.1(TP) SITE6.E10(AVDD33_RTC)
S6_PWR_F005: 6CA7.1 6CA8.1 6CC70.1 6CC71.1 6CC73.1 6SA8.1 6TP_DPS6.1(TP) SITE6.G18(VDDP3318_PM) SITE6.N17(VDDP3318_P0) SITE6.P3(VDDP3318_P2)
S6_PWR_F006: 6CA24.1 6CA25.1 6CC101.1 6CC103.1 6CC105.1 6SA9.1 6TP_DPS7.1(TP) SITE6.T13(VDD2_DRAM[0]) SITE6.T14(VDD2_DRAM[1]) SITE6.U13(VDD2_DRAM[2])
S6_PWR_F007: 6CA36.1 6CA37.1 6CC211.1 6CC212.1 6CC213.1 6SA23.1 6TP_DPS8.1(TP) SITE6.T10(VDDQ_DRAM[0]) SITE6.T11(VDDQ_DRAM[1]) SITE6.U11(VDDQ_DRAM[2])
S6_PWR_F008: 6CA38.1 6CA39.1 6CC220.1 6SA25.1 6TP_DPS9.1(TP) SITE6.K19(AVDD18_XTAL)
S6_PWR_GS001: 6SA15.2
S6_PWR_GS002: 6SA18.2
S6_PWR_GS003: 6SA20.2
S6_PWR_GS004: 6SA22.2
S6_PWR_GS005: 6SA7.2
S6_PWR_GS006: 6SA10.2
S6_PWR_GS007: 6SA24.2
S6_PWR_GS008: 6SA26.2
S6_PWR_M_F001: 6CA1.1 6CA2.1 6CC1.1 6CC2.1 6CC3.1 6CC4.1 6CC5.1 6CC6.1 6CC7.1 6CC8.1 6CC9.1 6CC12.1 6CC13.1 6CC14.1 6CC15.1 6CC16.1 6CC130.1 6CC214.1 6CC215.1 6CC216.1 6CC217.1 6CC218.1 6CC219.1 6K96.4 6K96.9 6SA1.1 6TP_DPS1.1(TP) SITE6.F6(AVDDL_MIPI_RX) SITE6.F7(VDD_CPU[0]) SITE6.F8(VDD_CPU[1]) SITE6.G6(AVDDL_MIPI_TX) SITE6.G7(VDD_CPU[2]) SITE6.G8(VDD_CPU[3]) SITE6.G10(VDD[0]) SITE6.G11(VDD[1]) SITE6.H7(VDD_CPU[4]) SITE6.H8(VDD_CPU[5]) SITE6.H10(VDD[2]) SITE6.H11(VDD[3]) SITE6.H12(VDD[4]) SITE6.J10(VDD[5]) SITE6.J11(VDD[6]) SITE6.J12(VDD[7]) SITE6.J13(VDD[8]) SITE6.K10(VDD[9]) SITE6.K11(VDD[10]) SITE6.K12(VDD[11]) SITE6.K13(VDD[12])
S6_PWR_M_GS001: 6SA2.2
S6_PWR_M_S001: 6SA1.2
S6_PWR_S001: 6SA16.2
S6_PWR_S002: 6SA17.2
S6_PWR_S003: 6SA19.2
S6_PWR_S004: 6SA21.2
S6_PWR_S005: 6SA8.2
S6_PWR_S006: 6SA9.2
S6_PWR_S007: 6SA23.2
S6_PWR_S008: 6SA25.2
UT1_UP5V: 4K96.1(V+) 5K96.1(V+) 6K96.1(V+) ; also on sheet 2 4 12 14 17 19 20 21 22 23 24 25 26 27 28 30 31 32 33 34 35 36 37
N22572177: 4CA19.1 4K96.5 4K96.8
N22578322: 4R172.1 4U408.A1(GPU_SEL)
N22578325: 4R661.1 4U408.B7(/XSD)
N22578329: 4R662.1 4U409.A1(GPU_SEL)
N22578332: 4R663.1 4U409.B7(/XSD)
N22578356: 4R672.1 4U409.C2(DDC_AUX_SEL)
N22578394: 4R659.1 4U408.C2(DDC_AUX_SEL)
N22578502: 4R1104.1 4U455.A1(GPU_SEL)
N22578505: 4R1101.1 4U455.B7(/XSD)
N22578509: 4R1102.1 4U456.A1(GPU_SEL)
N22578512: 4R1098.1 4U456.B7(/XSD)
N22578536: 4R1108.1 4U456.C2(DDC_AUX_SEL)
N22578574: 4R1105.1 4U455.C2(DDC_AUX_SEL)
N22578682: 4BDB5.1 4R234.1
N22578684: 4BDB6.1 4R1117.1
N22578686: 4BDB8.1 4R1118.1
N22578688: 4BDB7.1 4R1119.1
N22580039: 5CA19.1 5K96.5 5K96.8
N22586184: 5R172.1 5U408.A1(GPU_SEL)
N22586187: 5R661.1 5U408.B7(/XSD)
N22586191: 5R662.1 5U409.A1(GPU_SEL)
N22586194: 5R663.1 5U409.B7(/XSD)
N22586218: 5R672.1 5U409.C2(DDC_AUX_SEL)
N22586256: 5R659.1 5U408.C2(DDC_AUX_SEL)
N22586364: 5R1104.1 5U455.A1(GPU_SEL)
N22586367: 5R1101.1 5U455.B7(/XSD)
N22586371: 5R1102.1 5U456.A1(GPU_SEL)
N22586374: 5R1098.1 5U456.B7(/XSD)
N22586398: 5R1108.1 5U456.C2(DDC_AUX_SEL)
N22586436: 5R1105.1 5U455.C2(DDC_AUX_SEL)
N22586544: 5BDB5.1 5R234.1
N22586546: 5BDB6.1 5R1117.1
N22586548: 5BDB8.1 5R1118.1
N22586550: 5BDB7.1 5R1119.1
N22587901: 6CA19.1 6K96.5 6K96.8

Not connected (* = marked no-connect by the designer): 4K96 3* 10*; 4U408 A8(DIN1_3+)* A9(DIN1_3-)* F1(DOUT_3-)* F2(DOUT_3+)* F8(DIN2_3+)* F9(DIN2_3-)* H1(AUX-)* H2(AUX+)* H3(HPD_2)* H5(DDC_CLK2)* H6(DAUX2+)* H8(DDC_CLK1)* H9(DAUX1+)* J1(HPDIN)* J2(HPD_1)* J3(DDC_CLK)* J5(DDC_DAT2)* J6(DAUX2-)* J7(DDC_DAT)* J8(DDC_DAT1)* J9(DAUX1-)*; 4U409 A8(DIN1_3+)* A9(DIN1_3-)* F1(DOUT_3-)* F2(DOUT_3+)* F8(DIN2_3+)* F9(DIN2_3-)* H1(AUX-)* H2(AUX+)* H3(HPD_2)* H5(DDC_CLK2)* H6(DAUX2+)* H8(DDC_CLK1)* H9(DAUX1+)* J1(HPDIN)* J2(HPD_1)* J3(DDC_CLK)* J5(DDC_DAT2)* J6(DAUX2-)* J7(DDC_DAT)* J8(DDC_DAT1)* J9(DAUX1-)*; 4U455 A8(DIN1_3+)* A9(DIN1_3-)* F1(DOUT_3-)* F2(DOUT_3+)* F8(DIN2_3+)* F9(DIN2_3-)* H1(AUX-)* H2(AUX+)* H3(HPD_2)* H5(DDC_CLK2)* H6(DAUX2+)* H8(DDC_CLK1)* H9(DAUX1+)* J1(HPDIN)* J2(HPD_1)* J3(DDC_CLK)* J5(DDC_DAT2)* J6(DAUX2-)* J7(DDC_DAT)* J8(DDC_DAT1)* J9(DAUX1-)*; 4U456 A6(DIN1_2-)* A8(DIN1_3+)* A9(DIN1_3-)* B6(DIN1_2+)* E1(DOUT_2-)* E2(DOUT_2+)* E8(DIN2_2+)* E9(DIN2_2-)* F1(DOUT_3-)* F2(DOUT_3+)* F8(DIN2_3+)* F9(DIN2_3-)* H1(AUX-)* H2(AUX+)* H3(HPD_2)* H5(DDC_CLK2)* H6(DAUX2+)* H8(DDC_CLK1)* H9(DAUX1+)* J1(HPDIN)* J2(HPD_1)* J3(DDC_CLK)* J5(DDC_DAT2)* J6(DAUX2-)* J7(DDC_DAT)* J8(DDC_DAT1)* J9(DAUX1-)*; 5K96 3* 10*; 5U408 A8(DIN1_3+)* A9(DIN1_3-)* F1(DOUT_3-)* F2(DOUT_3+)* F8(DIN2_3+)* F9(DIN2_3-)* H1(AUX-)* H2(AUX+)* H3(HPD_2)* H5(DDC_CLK2)* H6(DAUX2+)* H8(DDC_CLK1)* H9(DAUX1+)* J1(HPDIN)* J2(HPD_1)* J3(DDC_CLK)* J5(DDC_DAT2)* J6(DAUX2-)* J7(DDC_DAT)* J8(DDC_DAT1)* J9(DAUX1-)*; 5U409 A8(DIN1_3+)* A9(DIN1_3-)* F1(DOUT_3-)* F2(DOUT_3+)* F8(DIN2_3+)* F9(DIN2_3-)* H1(AUX-)* H2(AUX+)* H3(HPD_2)* H5(DDC_CLK2)* H6(DAUX2+)* H8(DDC_CLK1)* H9(DAUX1+)* J1(HPDIN)* J2(HPD_1)* J3(DDC_CLK)* J5(DDC_DAT2)* J6(DAUX2-)* J7(DDC_DAT)* J8(DDC_DAT1)* J9(DAUX1-)*; 5U455 A8(DIN1_3+)* A9(DIN1_3-)* F1(DOUT_3-)* F2(DOUT_3+)* F8(DIN2_3+)* F9(DIN2_3-)* H1(AUX-)* H2(AUX+)* H3(HPD_2)* H5(DDC_CLK2)* H6(DAUX2+)* H8(DDC_CLK1)* H9(DAUX1+)* J1(HPDIN)* J2(HPD_1)* J3(DDC_CLK)* J5(DDC_DAT2)* J6(DAUX2-)* J7(DDC_DAT)* J8(DDC_DAT1)* J9(DAUX1-)*; 5U456 A6(DIN1_2-)* A8(DIN1_3+)* A9(DIN1_3-)* B6(DIN1_2+)* E1(DOUT_2-)* E2(DOUT_2+)* E8(DIN2_2+)* E9(DIN2_2-)* F1(DOUT_3-)* F2(DOUT_3+)* F8(DIN2_3+)* F9(DIN2_3-)* H1(AUX-)* H2(AUX+)* H3(HPD_2)* H5(DDC_CLK2)* H6(DAUX2+)* H8(DDC_CLK1)* H9(DAUX1+)* J1(HPDIN)* J2(HPD_1)* J3(DDC_CLK)* J5(DDC_DAT2)* J6(DAUX2-)* J7(DDC_DAT)* J8(DDC_DAT1)* J9(DAUX1-)*; 6K96 3* 10*

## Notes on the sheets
sheet 6
- 1.53A/0.7V/0.8V
- 0.05A/0.7V/0.8V
- 0.7A/1.8V
- 0.01A/3.3V
- 200uA/3.3V
- 0.75A/3.3V/1.8V
- 0.1A/1.1V
- 0.03A/0.8V
- 0.02A/1.8V
- Trace Width: 20 mil
sheet 7
- 100 ohm DIFF
- 2023.10.30
- 100 ohm DIFF
- 2023.10.30
sheet 8
- 1.53A/0.7V/0.8V
- 0.05A/0.7V/0.8V
- 0.7A/1.8V
- 0.01A/3.3V
- 200uA/3.3V
- 0.75A/3.3V/1.8V
- 0.1A/1.1V
- 0.03A/0.8V
- 0.02A/1.8V
- Trace Width: 20 mil
sheet 9
- 100 ohm DIFF
- 2023.10.30
- 100 ohm DIFF
- 2023.10.30
sheet 10
- 1.53A/0.7V/0.8V
- 0.05A/0.7V/0.8V
- 0.7A/1.8V
- 0.01A/3.3V
- 200uA/3.3V
- 0.75A/3.3V/1.8V
- 0.1A/1.1V
- 0.03A/0.8V
- 0.02A/1.8V
- Trace Width: 20 mil
